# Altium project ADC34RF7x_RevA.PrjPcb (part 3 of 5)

## Sheet ADC34RF7x_MUX_RevA.SchDoc: MUXes
size 431 x 279 mm; Date: Not shown in title block; ApprovedBy: Not shown in title block; CheckedBy: Not shown in title block; Author: Not shown in title block; CompanyName: Not shown in title block; DrawnBy: CW; Engineer: Not shown in title block; Organization: Not shown in title block; Address1: Not shown in title block; Address2: Not shown in title block; Address3: Not shown in title block; Address4: Not shown in title block; DocumentNumber: 10; Revision: Use project parameter SCH_Rev; SheetNumber: 10; SheetTotal: 19; PageSetup: Record=PageOptions¦CenterHorizontal=True¦CenterVertical=True¦PrintScale=1.00¦XCorrection=1.00¦YCorrection=1.00¦PrintKind=0¦BorderSize=5000000¦LeftOffset=0¦BottomOffset=0¦Orientation=2¦PaperLength=1000¦PaperWidth=1000¦Scale=100¦PaperSource=15¦PrintQuality=600¦MediaType=1¦DitherType=10¦PaperKind=Letter¦PrintScaleMode=1
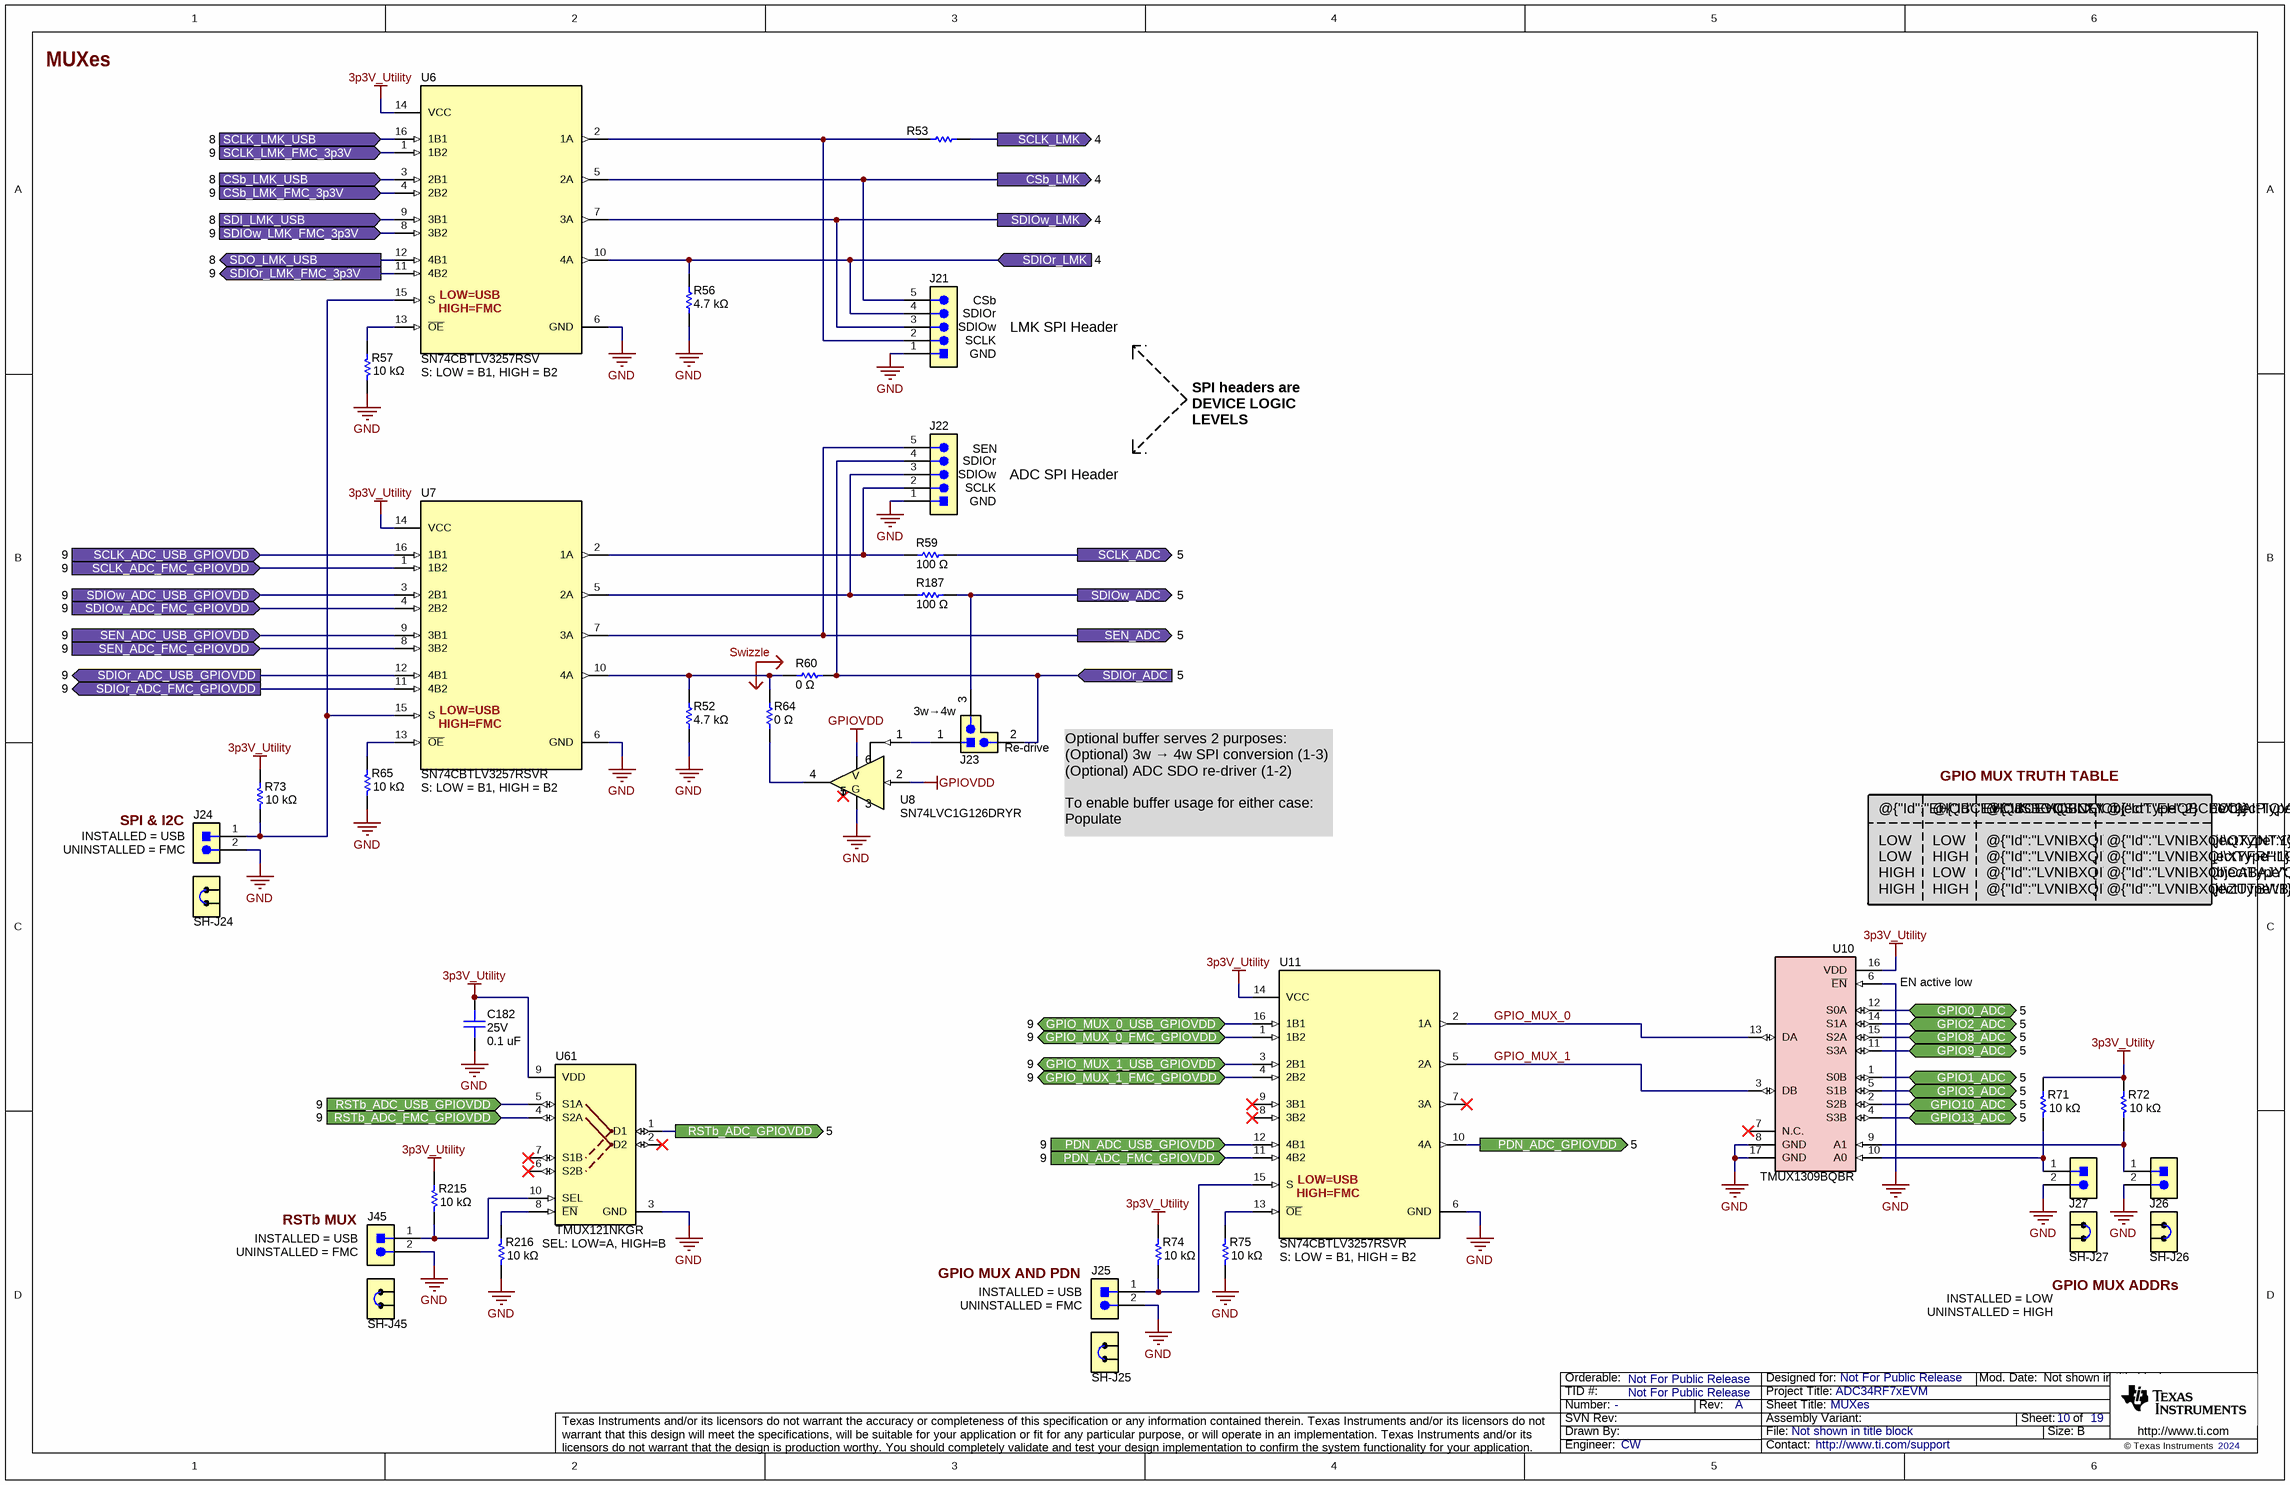
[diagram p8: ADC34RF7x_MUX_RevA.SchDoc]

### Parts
?  Swizzle  (graphical)
C182  value 0.1 uF  Voltage - Rated: 25V  [0201_cap]  (hidden comment: C0603X5R1E104K030BB)
J21  Text5: CSb  Text4: SDIOr  Text3: SDIOw  Text2: SCLK  Text1: GND  [HDR_5x1_TH_VT_50mil]  (hidden comment: GRPB051VWVN-RC)
J22  Text5: SEN  Text4: SDIOr  Text3: SDIOw  Text2: SCLK  Text1: GND  [HDR_5x1_TH_VT_50mil]  (hidden comment: GRPB051VWVN-RC)
J23  Text3: 3w→4w  Text2: Re-drive  [l-header]  (hidden comment: L-Header)
J24  GRPB021VWVN-RC  [PBC02SAAN]  (value not drawn)
J25  GRPB021VWVN-RC  [PBC02SAAN]  (value not drawn)
J26  GRPB021VWVN-RC  [PBC02SAAN]  (value not drawn)
J27  GRPB021VWVN-RC  [PBC02SAAN]  (value not drawn)
J45  GRPB021VWVN-RC  [PBC02SAAN]  (value not drawn)
R52  value 4.7 kΩ  [0201]  (hidden comment: ERJ-1GNF4701C)
R53  ERJ-1GNF1000C  [0201]  (value not drawn)
R56  value 4.7 kΩ  [0201]  (hidden comment: ERJ-1GNF4701C)
R57  value 10 kΩ  [0201]  (hidden comment: ERJ-1GNF1002C)
R59  value 100 Ω  [0201]  (hidden comment: ERJ-1GNF1000C)
R60  value 0 Ω  [0402L]  (hidden comment: ERJ-2GE0R00X)
R64  value 0 Ω  [0402L]  (hidden comment: ERJ-2GE0R00X)
R65  value 10 kΩ  [0201]  (hidden comment: ERJ-1GNF1002C)
R71  value 10 kΩ  [0201]  (hidden comment: ERJ-1GNF1002C)
R72  value 10 kΩ  [0201]  (hidden comment: ERJ-1GNF1002C)
R73  value 10 kΩ  [0201]  (hidden comment: ERJ-1GNF1002C)
R74  value 10 kΩ  [0201]  (hidden comment: ERJ-1GNF1002C)
R75  value 10 kΩ  [0201]  (hidden comment: ERJ-1GNF1002C)
R187  value 100 Ω  [0201]  (hidden comment: ERJ-1GNF1000C)
R215  value 10 kΩ  [0201]  (hidden comment: ERJ-1GNF1002C)
R216  value 10 kΩ  [0201]  (hidden comment: ERJ-1GNF1002C)
SH-J24  SPC02SYAN  [SPC02SYAN]  (value not drawn)
SH-J25  SPC02SYAN  [SPC02SYAN]  (value not drawn)
SH-J26  SPC02SYAN  [SPC02SYAN]  (value not drawn)
SH-J27  SPC02SYAN  [SPC02SYAN]  (value not drawn)
SH-J45  SPC02SYAN  [SPC02SYAN]  (value not drawn)
U6  SN74CBTLV3257RSV  Text1: S: LOW = B1, HIGH = B2  [RSV0016A]
U7  SN74CBTLV3257RSVR  Text1: S: LOW = B1, HIGH = B2  [RSV0016A]
U8  SN74LVC1G126DRYR  [DRY0006A]
U10  TMUX1309BQBR  [BQB0016A-MFG]
U11  SN74CBTLV3257RSVR  Text1: S: LOW = B1, HIGH = B2  [RSV0016A]
U61  TMUX121NKGR  Text1: SEL: LOW=A, HIGH=B  [NKG0010A]

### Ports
CSb_LMK (out, see 4), CSb_LMK_FMC_3p3V (in, see 9), CSb_LMK_USB (in, see 8), GPIO0_ADC (bidir, see 5), GPIO1_ADC (bidir, see 5), GPIO2_ADC (bidir, see 5), GPIO3_ADC (bidir, see 5), GPIO8_ADC (bidir, see 5), GPIO9_ADC (bidir, see 5), GPIO10_ADC (bidir, see 5), GPIO13_ADC (bidir, see 5), GPIO_MUX_0_FMC_GPIOVDD (bidir, see 9), GPIO_MUX_0_USB_GPIOVDD (bidir, see 9), GPIO_MUX_1_FMC_GPIOVDD (bidir, see 9), GPIO_MUX_1_USB_GPIOVDD (bidir, see 9), PDN_ADC_FMC_GPIOVDD (in, see 9), PDN_ADC_GPIOVDD (out, see 5), PDN_ADC_USB_GPIOVDD (in, see 9), RSTb_ADC_FMC_GPIOVDD (in, see 9), RSTb_ADC_GPIOVDD (out, see 5), RSTb_ADC_USB_GPIOVDD (in, see 9), SCLK_ADC (out, see 5), SCLK_ADC_FMC_GPIOVDD (in, see 9), SCLK_ADC_USB_GPIOVDD (in, see 9), SCLK_LMK (out, see 4), SCLK_LMK_FMC_3p3V (in, see 9), SCLK_LMK_USB (in, see 8), SDI_LMK_USB (in, see 8), SDIOr_ADC (in, see 5), SDIOr_ADC_FMC_GPIOVDD (out, see 9), SDIOr_ADC_USB_GPIOVDD (out, see 9), SDIOr_LMK (in, see 4), SDIOr_LMK_FMC_3p3V (out, see 9), SDIOw_ADC (out, see 5), SDIOw_ADC_FMC_GPIOVDD (in, see 9), SDIOw_ADC_USB_GPIOVDD (in, see 9), SDIOw_LMK (out, see 4), SDIOw_LMK_FMC_3p3V (in, see 9), SDO_LMK_USB (out, see 8), SEN_ADC (out, see 5), SEN_ADC_FMC_GPIOVDD (in, see 9), SEN_ADC_USB_GPIOVDD (in, see 9)

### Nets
3p3V_Utility: C182.2 R71.2 R72.2 R73.2 R74.2 R215.2 U6.14(VCC) U7.14(VCC) U10.16(VDD) U11.14(VCC) U61.9(VDD)
GND: C182.1 J21.1 J22.1 J24.2 J25.2 J26.2 J27.2 J45.2 R52.1 R56.1 R57.1 R65.1 R75.1 R216.1 U6.6(GND) U7.6(GND) U8.3(GND) U10.6(~{EN}) U10.8(GND) U10.17(GND) U11.6(GND) U61.3(GND)
GPIOVDD: U8.2(A) U8.6(VCC)
CSb_LMK: J21.5 U6.5(2A) ; port CSb_LMK
CSb_LMK_FMC_3p3V: U6.4(2B2) ; port CSb_LMK_FMC_3p3V
CSb_LMK_USB: U6.3(2B1) ; port CSb_LMK_USB
GPIO0_ADC: U10.12(S0A) ; port GPIO0_ADC
GPIO1_ADC: U10.1(S0B) ; port GPIO1_ADC
GPIO2_ADC: U10.14(S1A) ; port GPIO2_ADC
GPIO3_ADC: U10.5(S1B) ; port GPIO3_ADC
GPIO8_ADC: U10.15(S2A) ; port GPIO8_ADC
GPIO9_ADC: U10.11(S3A) ; port GPIO9_ADC
GPIO10_ADC: U10.2(S2B) ; port GPIO10_ADC
GPIO13_ADC: U10.4(S3B) ; port GPIO13_ADC
GPIO_MUX_0: U10.13(DA) U11.2(1A)
GPIO_MUX_0_FMC_GPIOVDD: U11.1(1B2) ; port GPIO_MUX_0_FMC_GPIOVDD
GPIO_MUX_0_USB_GPIOVDD: U11.16(1B1) ; port GPIO_MUX_0_USB_GPIOVDD
GPIO_MUX_1: U10.3(DB) U11.5(2A)
GPIO_MUX_1_FMC_GPIOVDD: U11.4(2B2) ; port GPIO_MUX_1_FMC_GPIOVDD
GPIO_MUX_1_USB_GPIOVDD: U11.3(2B1) ; port GPIO_MUX_1_USB_GPIOVDD
PDN_ADC_FMC_GPIOVDD: U11.11(4B2) ; port PDN_ADC_FMC_GPIOVDD
PDN_ADC_GPIOVDD: U11.10(4A) ; port PDN_ADC_GPIOVDD
PDN_ADC_USB_GPIOVDD: U11.12(4B1) ; port PDN_ADC_USB_GPIOVDD
RSTb_ADC_FMC_GPIOVDD: U61.4(S2A) ; port RSTb_ADC_FMC_GPIOVDD
RSTb_ADC_GPIOVDD: U61.1(D1) ; port RSTb_ADC_GPIOVDD
RSTb_ADC_USB_GPIOVDD: U61.5(S1A) ; port RSTb_ADC_USB_GPIOVDD
SCLK_ADC: R59.2 ; port SCLK_ADC
SCLK_ADC_FMC_GPIOVDD: U7.1(1B2) ; port SCLK_ADC_FMC_GPIOVDD
SCLK_ADC_USB_GPIOVDD: U7.16(1B1) ; port SCLK_ADC_USB_GPIOVDD
SCLK_LMK: R53.1 ; port SCLK_LMK
SCLK_LMK_FMC_3p3V: U6.1(1B2) ; port SCLK_LMK_FMC_3p3V
SCLK_LMK_USB: U6.16(1B1) ; port SCLK_LMK_USB
SDI_LMK_USB: U6.9(3B1) ; port SDI_LMK_USB
SDIOr_ADC: J22.4 J23.2 R60.2 ; port SDIOr_ADC
SDIOr_ADC_FMC_GPIOVDD: U7.11(4B2) ; port SDIOr_ADC_FMC_GPIOVDD
SDIOr_ADC_USB_GPIOVDD: U7.12(4B1) ; port SDIOr_ADC_USB_GPIOVDD
SDIOr_LMK: J21.4 R56.2 U6.10(4A) ; port SDIOr_LMK
SDIOr_LMK_FMC_3p3V: U6.11(4B2) ; port SDIOr_LMK_FMC_3p3V
SDIOw_ADC: J23.3 R187.2 ; port SDIOw_ADC
SDIOw_ADC_FMC_GPIOVDD: U7.4(2B2) ; port SDIOw_ADC_FMC_GPIOVDD
SDIOw_ADC_USB_GPIOVDD: U7.3(2B1) ; port SDIOw_ADC_USB_GPIOVDD
SDIOw_LMK: J21.3 U6.7(3A) ; port SDIOw_LMK
SDIOw_LMK_FMC_3p3V: U6.8(3B2) ; port SDIOw_LMK_FMC_3p3V
SDO_LMK_USB: U6.12(4B1) ; port SDO_LMK_USB
SEN_ADC: J22.5 U7.7(3A) ; port SEN_ADC
SEN_ADC_FMC_GPIOVDD: U7.8(3B2) ; port SEN_ADC_FMC_GPIOVDD
SEN_ADC_USB_GPIOVDD: U7.9(3B1) ; port SEN_ADC_USB_GPIOVDD
NetJ21_2: J21.2 R53.2 U6.2(1A)
NetJ22_2: J22.2 R59.1 U7.2(1A)
NetJ22_3: J22.3 R187.1 U7.5(2A)
NetJ23_1: J23.1 U8.1(~{OE})
NetJ24_1: J24.1 R73.1 U6.15(S) U7.15(S)
NetJ25_1: J25.1 R74.1 U11.15(S)
NetJ26_1: J26.1 R72.1 U10.9(A1)
NetJ27_1: J27.1 R71.1 U10.10(A0)
NetJ45_1: J45.1 R215.1 U61.10(SEL)
NetR52_2: R52.2 R60.1 R64.2 U7.10(4A)
NetR57_2: R57.2 U6.13(~{OE})
NetR64_1: R64.1 U8.4(Y)
NetR65_2: R65.2 U7.13(~{OE})
NetR75_2: R75.2 U11.13(~{OE})
NetR216_2: R216.2 U61.8(~{EN})

Not connected (* = marked no-connect by the designer): U8 5(NC)*; U10 7(N.C.)*; U11 7(3A)* 8(3B2)* 9(3B1)*; U61 2(D2)* 6(S2B)* 7(S1B)*

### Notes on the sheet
- (near U6) LOW=USB
- (near U6) HIGH=FMC
- LMK SPI Header
- SPI headers are DEVICE LOGIC LEVELS
- ADC SPI Header
- (near U7) LOW=USB
- (near U7) HIGH=FMC
- (near J24) SPI & I2C
- (near J24) INSTALLED = USB
- Optional buffer serves 2 purposes:
  (Optional) 3w → 4w SPI conversion (1-3)
  (Optional) ADC SDO re-driver (1-2)
  To enable buffer usage for either case: Populate @{"Id":"EHQBCEVC\QQRHBLRB","ObjectType":2} and depopulate @{"Id":"EHQBCEVC\ZQNBUIIU","ObjectType":2}
- GPIO MUX TRUTH TABLE
- UNINSTALLED = FMC
- @{"Id":"EHQBCEVC\JSBOQSIN","ObjectType":2}
  LOW
  LOW
  HIGH
  HIGH
- @{"Id":"EHQBCEVC\FLXYZYRI","ObjectType":2}
  LOW
  HIGH
  LOW
  HIGH
- @{"Id":"EHQBCEVC\FQXZMCJW","ObjectType":1}
  @{"Id":"LVNIBXQI\KMIXACKC","ObjectType":1}
  @{"Id":"LVNIBXQI\CEYJVZJK","ObjectType":1}
  @{"Id":"LVNIBXQI\UZKQOAMN","ObjectType":1}
  @{"Id":"LVNIBXQI\EZFJRBJM","ObjectType":1}
- @{"Id":"EHQBCEVC\AIPIQVSM","ObjectType":1}
  @{"Id":"LVNIBXQI\QXZNTYOS","ObjectType":1}
  @{"Id":"LVNIBXQI\XYFRHLOS","ObjectType":1}
  @{"Id":"LVNIBXQI\CABAJYQK","ObjectType":1}
  @{"Id":"LVNIBXQI\ZUTBWBLA","ObjectType":1}
- (near U10) EN active low
- (near J45) RSTb MUX
- (near J45) INSTALLED = USB
- (near U11) LOW=USB
- (near U11) HIGH=FMC
- (near J25) GPIO MUX AND PDN
- (near J25) INSTALLED = USB
- INSTALLED = LOW
- GPIO MUX ADDRs
- UNINSTALLED = HIGH

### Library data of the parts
? = Swizzle: Schematic notation to show that the pads of two components should be overlapped
C182 = capcc01294: CAP CER 0.1UF 25V X5R 0201; Manufacturer: TDK Corporation; CompType: Capacitor Ceramic; Tolerance: ±10%; SizeX_mm: 0.6; SizeY_mm: 0.3; SizeZ_mm: 0.33
J21 J22 = GRPB051VWVN-RC: Header, 50mil, 5x1, Gold, TH; Manufacturer: Sullins Connector Solutions; Pitch (mm): 1.27
J23 = L-Header: "L" Configuration Headers Connector Header Through Hole 3 position 100mils; UniqueID: cmp00511; CompType: Wire Housing; Text1: BufferIn
J24-J27 J45 = TSW-102-14-L-S: Header, 100mil, 2x1, Gold, TH; Manufacturer: Samtec; Alt Manufacturer: Sullins Connector Solutions; UniqueID: cmp00014; Pitch (mm): 2.54
R52 R56 = RSMD020100508: RES SMD 4.7K OHM 1% 1/20W 0201; Manufacturer: Panasonic Electronic Components; CompType: Resistor SMD; Power (Watts): 0.05W, 1/20W; Temperature Coefficient: ±200ppm/°C
R53 = RSMD020100289: RES SMD 100 OHM 1% 1/20W 0201; Manufacturer: Panasonic Electronic Components; Value: 100 Ω; CompType: Resistor SMD; Power (Watts): 0.05W, 1/20W; Temperature Coefficient: ±200ppm/°C
R57 R65 R71-R75 R215 R216 = RSMD020100762: RES SMD 10K OHM 1% 1/20W 0201; Manufacturer: Panasonic Electronic Components; CompType: Resistor SMD; Power (Watts): 0.05W, 1/20W; Temperature Coefficient: ±200ppm/°C
R59 R187 = RSMD020100289: RES SMD 100 OHM 1% 1/20W 0201; Manufacturer: Panasonic Electronic Components; CompType: Resistor SMD; Power (Watts): 0.05W, 1/20W; Temperature Coefficient: ±200ppm/°C
R60 R64 = RSMD040200001: RES SMD 0 OHM JUMPER 1/10W 0402; Manufacturer: Panasonic Electronic Components; CompType: Resistor SMD; Power (Watts): 0.1W, 1/10W; SizeX_mm: 1; SizeY_mm: 0.5; SizeZ_mm: 0.4
SH-J24-SH-J27 SH-J45 = cmp00093: 2 (1 x 2) Position Shunt Connector Black Closed Top 0.100" (2.54mm) Gold; Manufacturer: Sullins; Value: 1x2; Note: You can "mate" this to a header by matching the designator.  i.e. use SH-J3 for header J3; Pitch (mm): 2.54
U6 = SN74CBTLV3257RSV: Low-Voltage 4-Bit 1-of-2 FET Multiplexer/Demultiplexe; PartNumber: SN74CBTLV3257RSVR; Manufacturer: Texas Instruments; UniqueID: cmp00269; CompType: MUX
U7 U11 = SN74CBTLV3257RSV: Low-Voltage 4-Bit 1-of-2 FET Multiplexer/Demultiplexe; Manufacturer: Texas Instruments; UniqueID: cmp00269; CompType: MUX
U8 = cmp00344: Low-Power Single Bus Buffer Gate With Tri-State Output; Manufacturer: Texas Instruments
U10 = TMUX1309BQBR: Bidirectional 4:1, 2-Channel Multiplexer with Injection Current Control; Manufacturer: Texas Instruments
U61 = TMUX121NKGR: 2-pF, 3.3-V, 2:1 (SPDT), 2-channel, switch with 1.8-V compatible logic; Manufacturer: Texas Instruments

## Sheet ADC34RF7x_SYSREF_FPGA_MUX_RevA.SchDoc
size 431 x 279 mm; Date: Not shown in title block; ApprovedBy: Not shown in title block; CheckedBy: Not shown in title block; Author: Not shown in title block; CompanyName: Not shown in title block; Engineer: Not shown in title block; Organization: Not shown in title block; Address1: Not shown in title block; Address2: Not shown in title block; Address3: Not shown in title block; Address4: Not shown in title block; DocumentNumber: 1; Revision: Use project parameter SCH_Rev; SheetNumber: 11; SheetTotal: 19; PageSetup: Record=PageOptions¦CenterHorizontal=True¦CenterVertical=True¦PrintScale=1.00¦XCorrection=1.00¦YCorrection=1.00¦PrintKind=0¦BorderSize=5000000¦LeftOffset=0¦BottomOffset=0¦Orientation=2¦PaperLength=1000¦PaperWidth=1000¦Scale=100¦PaperSource=15¦PrintQuality=600¦MediaType=1¦DitherType=10¦PaperKind=Letter¦PrintScaleMode=1
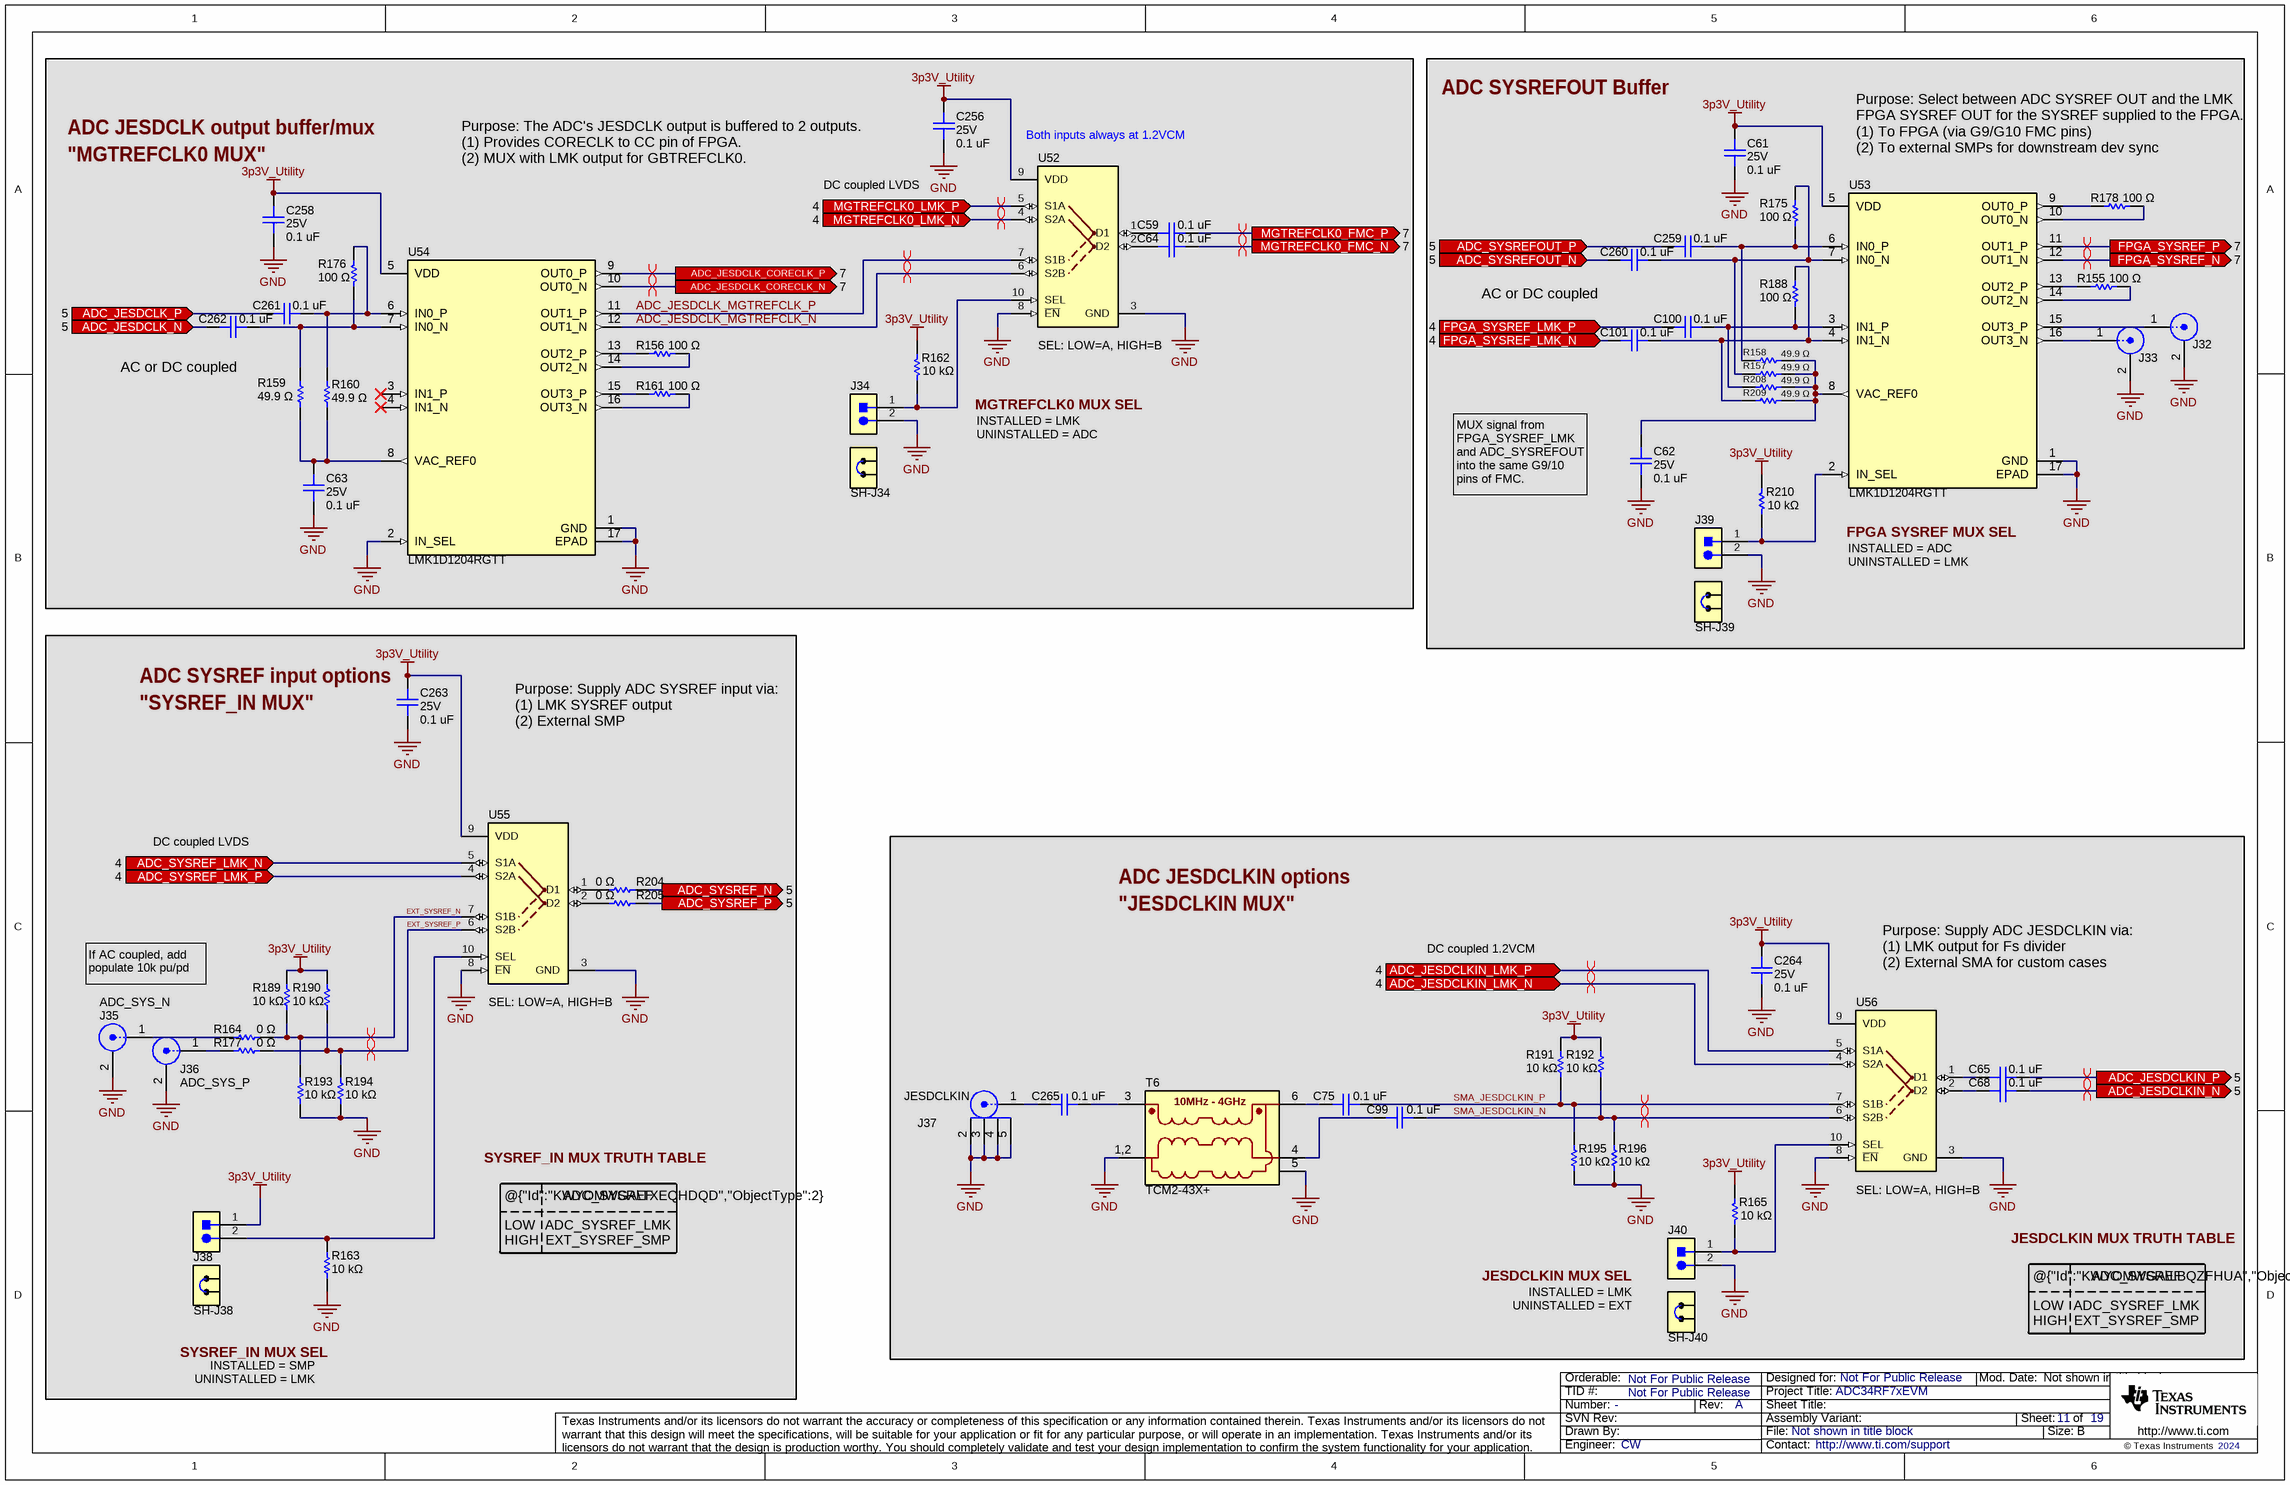
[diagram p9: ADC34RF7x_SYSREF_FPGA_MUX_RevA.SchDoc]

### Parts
C59  value 0.1 uF  [0201_cap]  (hidden comment: C0603X5R1E104K030BB)
C61  value 0.1 uF  Voltage - Rated: 25V  [0201_cap]  (hidden comment: C0603X5R1E104K030BB)
C62  value 0.1 uF  Voltage - Rated: 25V  [0201_cap]  (hidden comment: C0603X5R1E104K030BB)
C63  value 0.1 uF  Voltage - Rated: 25V  [0201_cap]  (hidden comment: C0603X5R1E104K030BB)
C64  value 0.1 uF  [0201_cap]  (hidden comment: C0603X5R1E104K030BB)
C65  value 0.1 uF  [0201_cap]  (hidden comment: C0603X5R1E104K030BB)
C68  value 0.1 uF  [0201_cap]  (hidden comment: C0603X5R1E104K030BB)
C75  value 0.1 uF  [0201_cap]  (hidden comment: 0201BB104KW160)
C99  value 0.1 uF  [0201_cap]  (hidden comment: 0201BB104KW160)
C100  value 0.1 uF  [0201_cap]  (hidden comment: C0603X5R1E104K030BB)
C101  value 0.1 uF  [0201_cap]  (hidden comment: C0603X5R1E104K030BB)
C256  value 0.1 uF  Voltage - Rated: 25V  [0201_cap]  (hidden comment: C0603X5R1E104K030BB)
C258  value 0.1 uF  Voltage - Rated: 25V  [0201_cap]  (hidden comment: C0603X5R1E104K030BB)
C259  value 0.1 uF  [0201_cap]  (hidden comment: C0603X5R1E104K030BB)
C260  value 0.1 uF  [0201_cap]  (hidden comment: C0603X5R1E104K030BB)
C261  value 0.1 uF  [0201_cap]  (hidden comment: C0603X5R1E104K030BB)
C262  value 0.1 uF  [0201_cap]  (hidden comment: C0603X5R1E104K030BB)
C263  value 0.1 uF  Voltage - Rated: 25V  [0201_cap]  (hidden comment: C0603X5R1E104K030BB)
C264  value 0.1 uF  Voltage - Rated: 25V  [0201_cap]  (hidden comment: C0603X5R1E104K030BB)
C265  value 0.1 uF  [0201_cap]  (hidden comment: 0201BB104KW160)
J32  0853050232  [Molex_0853050232]  (value not drawn)
J33  0853050232  [Molex_0853050232]  (value not drawn)
J34  GRPB021VWVN-RC  [PBC02SAAN]  (value not drawn)
J35  Text1: ADC_SYS_N  [Molex_0853050232]  (hidden comment: 0853050232)
J36  Text1: ADC_SYS_P  [Molex_0853050232]  (hidden comment: 0853050232)
J37  Text1: JESDCLKIN  [FP-132134-15_CONN_SMA_JACK-MFG]  (hidden comment: 132134-15)
J38  GRPB021VWVN-RC  [PBC02SAAN]  (value not drawn)
J39  GRPB021VWVN-RC  [PBC02SAAN]  (value not drawn)
J40  GRPB021VWVN-RC  [PBC02SAAN]  (value not drawn)
R155  value 100 Ω  [0201]  (hidden comment: ERJ-1GNF1000C)
R156  value 100 Ω  [0201]  (hidden comment: ERJ-1GNF1000C)
R157  value 49.9 Ω  [0201]  (hidden comment: ERJ-1GNF49R9C)
R158  value 49.9 Ω  [0201]  (hidden comment: ERJ-1GNF49R9C)
R159  value 49.9 Ω  [0201]  (hidden comment: ERJ-1GNF49R9C)
R160  value 49.9 Ω  [0201]  (hidden comment: ERJ-1GNF49R9C)
R161  value 100 Ω  [0201]  (hidden comment: ERJ-1GNF1000C)
R162  value 10 kΩ  [0201]  (hidden comment: ERJ-1GNF1002C)
R163  value 10 kΩ  [0201]  (hidden comment: ERJ-1GNF1002C)
R164  value 0 Ω  [0201]  (hidden comment: ERJ-1GN0R00C)
R165  value 10 kΩ  [0201]  (hidden comment: ERJ-1GNF1002C)
R175  value 100 Ω  [0201]  (hidden comment: ERJ-1GNF1000C)
R176  value 100 Ω  [0201]  (hidden comment: ERJ-1GNF1000C)
R177  value 0 Ω  [0201]  (hidden comment: ERJ-1GN0R00C)
R178  value 100 Ω  [0201]  (hidden comment: ERJ-1GNF1000C)
R188  value 100 Ω  [0201]  (hidden comment: ERJ-1GNF1000C)
R189  value 10 kΩ  [0201]  (hidden comment: ERJ-1GNF1002C)
R190  value 10 kΩ  [0201]  (hidden comment: ERJ-1GNF1002C)
R191  value 10 kΩ  [0201]  (hidden comment: ERJ-1GNF1002C)
R192  value 10 kΩ  [0201]  (hidden comment: ERJ-1GNF1002C)
R193  value 10 kΩ  [0201]  (hidden comment: ERJ-1GNF1002C)
R194  value 10 kΩ  [0201]  (hidden comment: ERJ-1GNF1002C)
R195  value 10 kΩ  [0201]  (hidden comment: ERJ-1GNF1002C)
R196  value 10 kΩ  [0201]  (hidden comment: ERJ-1GNF1002C)
R204  value 0 Ω  [0201]  (hidden comment: ERJ-1GN0R00C)
R205  value 0 Ω  [0201]  (hidden comment: ERJ-1GN0R00C)
R208  value 49.9 Ω  [0201]  (hidden comment: ERJ-1GNF49R9C)
R209  value 49.9 Ω  [0201]  (hidden comment: ERJ-1GNF49R9C)
R210  value 10 kΩ  [0201]  (hidden comment: ERJ-1GNF1002C)
SH-J34  SPC02SYAN  [SPC02SYAN]  (value not drawn)
SH-J38  SPC02SYAN  [SPC02SYAN]  (value not drawn)
SH-J39  SPC02SYAN  [SPC02SYAN]  (value not drawn)
SH-J40  SPC02SYAN  [SPC02SYAN]  (value not drawn)
T6  TCM2-43X+  [TCM2-43X+]
U52  Text1: SEL: LOW=A, HIGH=B  [NKG0010A]
U53  PartNumber: LMK1D1204RGTT  [RGT0016C]  (hidden comment: LMK1D1204)
U54  PartNumber: LMK1D1204RGTT  [RGT0016C]  (hidden comment: LMK1D1204)
U55  Text1: SEL: LOW=A, HIGH=B  [NKG0010A]
U56  Text1: SEL: LOW=A, HIGH=B  [NKG0010A]

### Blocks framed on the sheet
ADC SYSREFOUT Buffer: C61 C62 C100 C101 C259 C260 J32 J33 J39 R155 R157 R158 R175 R178 R188 R208-R210 SH-J39 U53

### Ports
ADC_JESDCLK_CORECLK_N (out, see 7), ADC_JESDCLK_CORECLK_P (out, see 7), ADC_JESDCLK_N (in, see 5), ADC_JESDCLK_P (in, see 5), ADC_JESDCLKIN_LMK_N (in, see 4), ADC_JESDCLKIN_LMK_P (in, see 4), ADC_JESDCLKIN_N (out, see 5), ADC_JESDCLKIN_P (out, see 5), ADC_SYSREF_LMK_N (in, see 4), ADC_SYSREF_LMK_P (in, see 4), ADC_SYSREF_N (out, see 5), ADC_SYSREF_P (out, see 5), ADC_SYSREFOUT_N (in, see 5), ADC_SYSREFOUT_P (in, see 5), FPGA_SYSREF_LMK_N (in, see 4), FPGA_SYSREF_LMK_P (in, see 4), FPGA_SYSREF_N (out, see 7), FPGA_SYSREF_P (out, see 7), MGTREFCLK0_FMC_N (out, see 7), MGTREFCLK0_FMC_P (out, see 7), MGTREFCLK0_LMK_N (in, see 4), MGTREFCLK0_LMK_P (in, see 4)

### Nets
3p3V_Utility: C61.2 C256.2 C258.2 C263.2 C264.2 J38.1 R162.2 R165.2 R189.2 R190.2 R191.2 R192.2 R210.2 U52.9(VDD) U53.5(VDD) U54.5(VDD) U55.9(VDD) U56.9(VDD)
GND: C61.1 C62.1 C63.1 C256.1 C258.1 C263.1 C264.1 J32.2 J33.2 J34.2 J35.2 J36.2 J37.2 J37.3 J37.4 J37.5 J39.2 J40.2 R163.1 R193.1 R194.1 R195.1 R196.1 T6.1,2(Primary) T6.5(NC) U52.3(GND) U52.8(~{EN}) U53.1(GND) U53.17(EPAD) U54.1(GND) U54.2(IN_SEL) U54.17(EPAD) U55.3(GND) U55.8(~{EN}) U56.3(GND) U56.8(~{EN})
ADC_JESDCLK_CORECLK_N: U54.10(OUT0_N) ; port ADC_JESDCLK_CORECLK_N
ADC_JESDCLK_CORECLK_P: U54.9(OUT0_P) ; port ADC_JESDCLK_CORECLK_P
ADC_JESDCLK_MGTREFCLK_N: U52.6(S2B) U54.12(OUT1_N)
ADC_JESDCLK_MGTREFCLK_P: U52.7(S1B) U54.11(OUT1_P)
ADC_JESDCLK_N: C262.2 ; port ADC_JESDCLK_N
ADC_JESDCLK_P: C261.2 ; port ADC_JESDCLK_P
ADC_JESDCLKIN_LMK_N: U56.4(S2A) ; port ADC_JESDCLKIN_LMK_N
ADC_JESDCLKIN_LMK_P: U56.5(S1A) ; port ADC_JESDCLKIN_LMK_P
ADC_JESDCLKIN_N: C68.1 ; port ADC_JESDCLKIN_N
ADC_JESDCLKIN_P: C65.1 ; port ADC_JESDCLKIN_P
ADC_SYSREF_LMK_N: U55.5(S1A) ; port ADC_SYSREF_LMK_N
ADC_SYSREF_LMK_P: U55.4(S2A) ; port ADC_SYSREF_LMK_P
ADC_SYSREF_N: R204.2 ; port ADC_SYSREF_N
ADC_SYSREF_P: R205.2 ; port ADC_SYSREF_P
ADC_SYSREFOUT_N: C260.2 ; port ADC_SYSREFOUT_N
ADC_SYSREFOUT_P: C259.2 ; port ADC_SYSREFOUT_P
EXT_SYSREF_N: R164.1 R189.1 R193.2 U55.7(S1B)
EXT_SYSREF_P: R177.1 R190.1 R194.2 U55.6(S2B)
FPGA_SYSREF_LMK_N: C101.2 ; port FPGA_SYSREF_LMK_N
FPGA_SYSREF_LMK_P: C100.2 ; port FPGA_SYSREF_LMK_P
FPGA_SYSREF_N: U53.12(OUT1_N) ; port FPGA_SYSREF_N
FPGA_SYSREF_P: U53.11(OUT1_P) ; port FPGA_SYSREF_P
MGTREFCLK0_FMC_N: C64.1 ; port MGTREFCLK0_FMC_N
MGTREFCLK0_FMC_P: C59.1 ; port MGTREFCLK0_FMC_P
MGTREFCLK0_LMK_N: U52.4(S2A) ; port MGTREFCLK0_LMK_N
MGTREFCLK0_LMK_P: U52.5(S1A) ; port MGTREFCLK0_LMK_P
SMA_JESDCLKIN_N: C99.1 R192.1 R196.2 U56.6(S2B)
SMA_JESDCLKIN_P: C75.1 R191.1 R195.2 U56.7(S1B)
NetC59_2: C59.2 U52.1(D1)
NetC62_2: C62.2 R157.1 R158.1 R208.1 R209.1 U53.8(VAC_REF0)
NetC63_2: C63.2 R159.1 R160.1 U54.8(VAC_REF0)
NetC64_2: C64.2 U52.2(D2)
NetC65_2: C65.2 U56.1(D1)
NetC68_2: C68.2 U56.2(D2)
NetC75_2: C75.2 T6.6(Secondary_Dot)
NetC99_2: C99.2 T6.4(Secondary)
NetC100_1: C100.1 R188.1 R208.2 U53.3(IN1_P)
NetC101_1: C101.1 R188.2 R209.2 U53.4(IN1_N)
NetC259_1: C259.1 R158.2 R175.2 U53.6(IN0_P)
NetC260_1: C260.1 R157.2 R175.1 U53.7(IN0_N)
NetC261_1: C261.1 R160.2 R176.2 U54.6(IN0_P)
NetC262_1: C262.1 R159.2 R176.1 U54.7(IN0_N)
NetC265_1: C265.1 T6.3(Primary_Dot)
NetC265_2: C265.2 J37.1
NetJ32_1: J32.1 U53.15(OUT3_P)
NetJ33_1: J33.1 U53.16(OUT3_N)
NetJ34_1: J34.1 R162.1 U52.10(SEL)
NetJ35_1: J35.1 R164.2
NetJ36_1: J36.1 R177.2
NetJ38_2: J38.2 R163.2 U55.10(SEL)
NetJ39_1: J39.1 R210.1 U53.2(IN_SEL)
NetJ40_1: J40.1 R165.1 U56.10(SEL)
NetR155_1: R155.1 U53.13(OUT2_P)
NetR155_2: R155.2 U53.14(OUT2_N)
NetR156_1: R156.1 U54.13(OUT2_P)
NetR156_2: R156.2 U54.14(OUT2_N)
NetR161_1: R161.1 U54.15(OUT3_P)
NetR161_2: R161.2 U54.16(OUT3_N)
NetR178_1: R178.1 U53.9(OUT0_P)
NetR178_2: R178.2 U53.10(OUT0_N)
NetR204_1: R204.1 U55.1(D1)
NetR205_1: R205.1 U55.2(D2)

Not connected (* = marked no-connect by the designer): U54 3(IN1_P)* 4(IN1_N)*

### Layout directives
differential pair: ADC_JESDCLK_CORECLK_N, ADC_JESDCLK_CORECLK_P, ADC_JESDCLK_MGTREFCLK_N, ADC_JESDCLK_MGTREFCLK_P, ADC_JESDCLKIN_LMK_N, ADC_JESDCLKIN_LMK_P, ADC_JESDCLKIN_N, ADC_JESDCLKIN_P, EXT_SYSREF_N, EXT_SYSREF_P, FPGA_SYSREF_N, FPGA_SYSREF_P, MGTREFCLK0_FMC_N, MGTREFCLK0_FMC_P, MGTREFCLK0_LMK_N, MGTREFCLK0_LMK_P, SMA_JESDCLKIN_N, SMA_JESDCLKIN_P

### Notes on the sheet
- ADC JESDCLK output buffer/mux
- (near C258) "MGTREFCLK0 MUX"
- (near U52) Both inputs always at 1.2VCM
- Purpose: Select between ADC SYSREF OUT and the LMK FPGA SYSREF OUT for the SYSREF supplied to the FPGA.
  (1) To FPGA (via G9/G10 FMC pins)
  (2) To external SMPs for downstream dev sync
- Purpose: The ADC's JESDCLK output is buffered to 2 outputs.
  (1) Provides CORECLK to CC pin of FPGA.
  (2) MUX with LMK output for GBTREFCLK0.
- (near C256) DC coupled LVDS
- AC or DC coupled
- (near C262) AC or DC coupled
- MGTREFCLK0 MUX SEL
- INSTALLED = LMK
- UNINSTALLED = ADC
- MUX signal from FPGA_SYSREF_LMK and ADC_SYSREFOUT into the same G9/10 pins of FMC.
- (near U53) FPGA SYSREF MUX SEL
- INSTALLED = ADC
- UNINSTALLED = LMK
- (near C263) ADC SYSREF input options
- "SYSREF_IN MUX"
- Purpose: Supply ADC SYSREF input via:
  (1) LMK SYSREF output
  (2) External SMP
- DC coupled LVDS
- ADC JESDCLKIN options
- "JESDCLKIN MUX"
- DC coupled 1.2VCM
- If AC coupled, add populate 10k pu/pd
- (near U56) Purpose: Supply ADC JESDCLKIN via:
  (1) LMK output for Fs divider
  (2) External SMA for custom cases
- (near T6) 10MHz - 4GHz
- SYSREF_IN MUX TRUTH TABLE
- JESDCLKIN MUX TRUTH TABLE
- @{"Id":"KWYOMWGA\TXEQHDQD","ObjectType":2}
  LOW
  HIGH
- ADC_SYSREF
  ADC_SYSREF_LMK
  EXT_SYSREF_SMP
- JESDCLKIN MUX SEL
- UNINSTALLED = EXT
- SYSREF_IN MUX SEL
- INSTALLED = SMP
- @{"Id":"KWYOMWGA\LBQZFHUA","ObjectType":2}
  LOW
  HIGH

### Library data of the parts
C59 C61-C65 C68 C100 C101 C256 C258-C264 = capcc01294: as C182 on sheet ADC34RF7x_MUX_RevA
C75 C99 C265 = 0201RFCaps0693: Broadband Capacitors; Manufacturer: Passive Plus; Alt PartNumber: GRM033C71C104ME14D; Alt Manufacturer: Murata Electronics; SizeZ_mm: 0.33; SizeY_mm: 0.3; CompType: Capactior RF; SizeX_mm: 0.58; Voltage - Rated: 16V; Tolerance: ±10%; Temperature Coefficient: C0G, NP0
J32 = cmp00032: SMP Connector Plug, Male Pin 50Ohm Surface Mount Solder; Manufacturer: Molex; SymbolCreator: a0799628; Cert_UL: Y; ContactFinish: Gold; CompType: RF Connector; CT: False; Voltage_V: 335V; Text1: ADC_SYSREFOUT_P
J33 = cmp00032: SMP Connector Plug, Male Pin 50Ohm Surface Mount Solder; Manufacturer: Molex; SymbolCreator: a0799628; Cert_UL: Y; ContactFinish: Gold; CompType: RF Connector; CT: False; Voltage_V: 335V; Text1: ADC_SYSREFOUT_N
J34 J38-J40 = TSW-102-14-L-S: as J24-J27 on sheet ADC34RF7x_MUX_RevA
J35 J36 = cmp00032: SMP Connector Plug, Male Pin 50Ohm Surface Mount Solder; Manufacturer: Molex; SymbolCreator: a0799628; Cert_UL: Y; ContactFinish: Gold; CompType: RF Connector; CT: False; Voltage_V: 335V
J37 = cmp00028: SMA Connector Jack, Female Socket 50Ohm Surface Mount, Through Hole Solder; Manufacturer: Amphenol RF; CompType: RF Connector
R155 R156 R161 R175 R176 R178 R188 = RSMD020100289: as R59 on sheet ADC34RF7x_MUX_RevA
R157-R160 R208 R209 = RSMD020100177: RES SMD 49.9 OHM 1% 1/20W 0201; Manufacturer: Panasonic Electronic Components; CompType: Resistor SMD; Power (Watts): 0.05W, 1/20W; Temperature Coefficient: ±200ppm/°C
R162 R163 R165 R189-R196 R210 = RSMD020100762: as R57 on sheet ADC34RF7x_MUX_RevA
R164 R177 R204 R205 = RSMD020101699: RES SMD 0 OHM JUMPER 1/20W 0201; Manufacturer: Panasonic Electronic Components; CompType: Resistor SMD; Power (Watts): 0.05W, 1/20W
SH-J34 SH-J38-SH-J40 = cmp00093: as SH-J24-SH-J27 on sheet ADC34RF7x_MUX_RevA
T6 = cmp00381: 1:2 CORE & WIRE Transformer, 10 - 4000 MHz, 50Ω; Manufacturer: Mini-Circuits; CompType: Balun
U52 U55 U56 = TMUX121NKGR: as U61 on sheet ADC34RF7x_MUX_RevA
U53 U54 = cmp00271: Texas Instruments; Manufacturer_Part_Number: LMK1D1204RGTR; CompType: Buffer

## Sheet ADC34RF7x_Power1_RevA.SchDoc: EVM Power 1
size 431 x 279 mm; Date: Not shown in title block; ApprovedBy: Not shown in title block; CheckedBy: Not shown in title block; Author: Not shown in title block; CompanyName: Not shown in title block; DrawnBy: CW; Engineer: Not shown in title block; Organization: Not shown in title block; Address1: Not shown in title block; Address2: Not shown in title block; Address3: Not shown in title block; Address4: Not shown in title block; DocumentNumber: 6; Revision: Use project parameter SCH_Rev; SheetNumber: 12; SheetTotal: 19; PageSetup: Record=PageOptions¦CenterHorizontal=True¦CenterVertical=True¦PrintScale=1.00¦XCorrection=1.00¦YCorrection=1.00¦PrintKind=0¦BorderSize=5000000¦LeftOffset=0¦BottomOffset=0¦Orientation=2¦PaperLength=1000¦PaperWidth=1000¦Scale=100¦PaperSource=15¦PrintQuality=600¦MediaType=1¦DitherType=10¦PaperKind=Letter¦PrintScaleMode=1
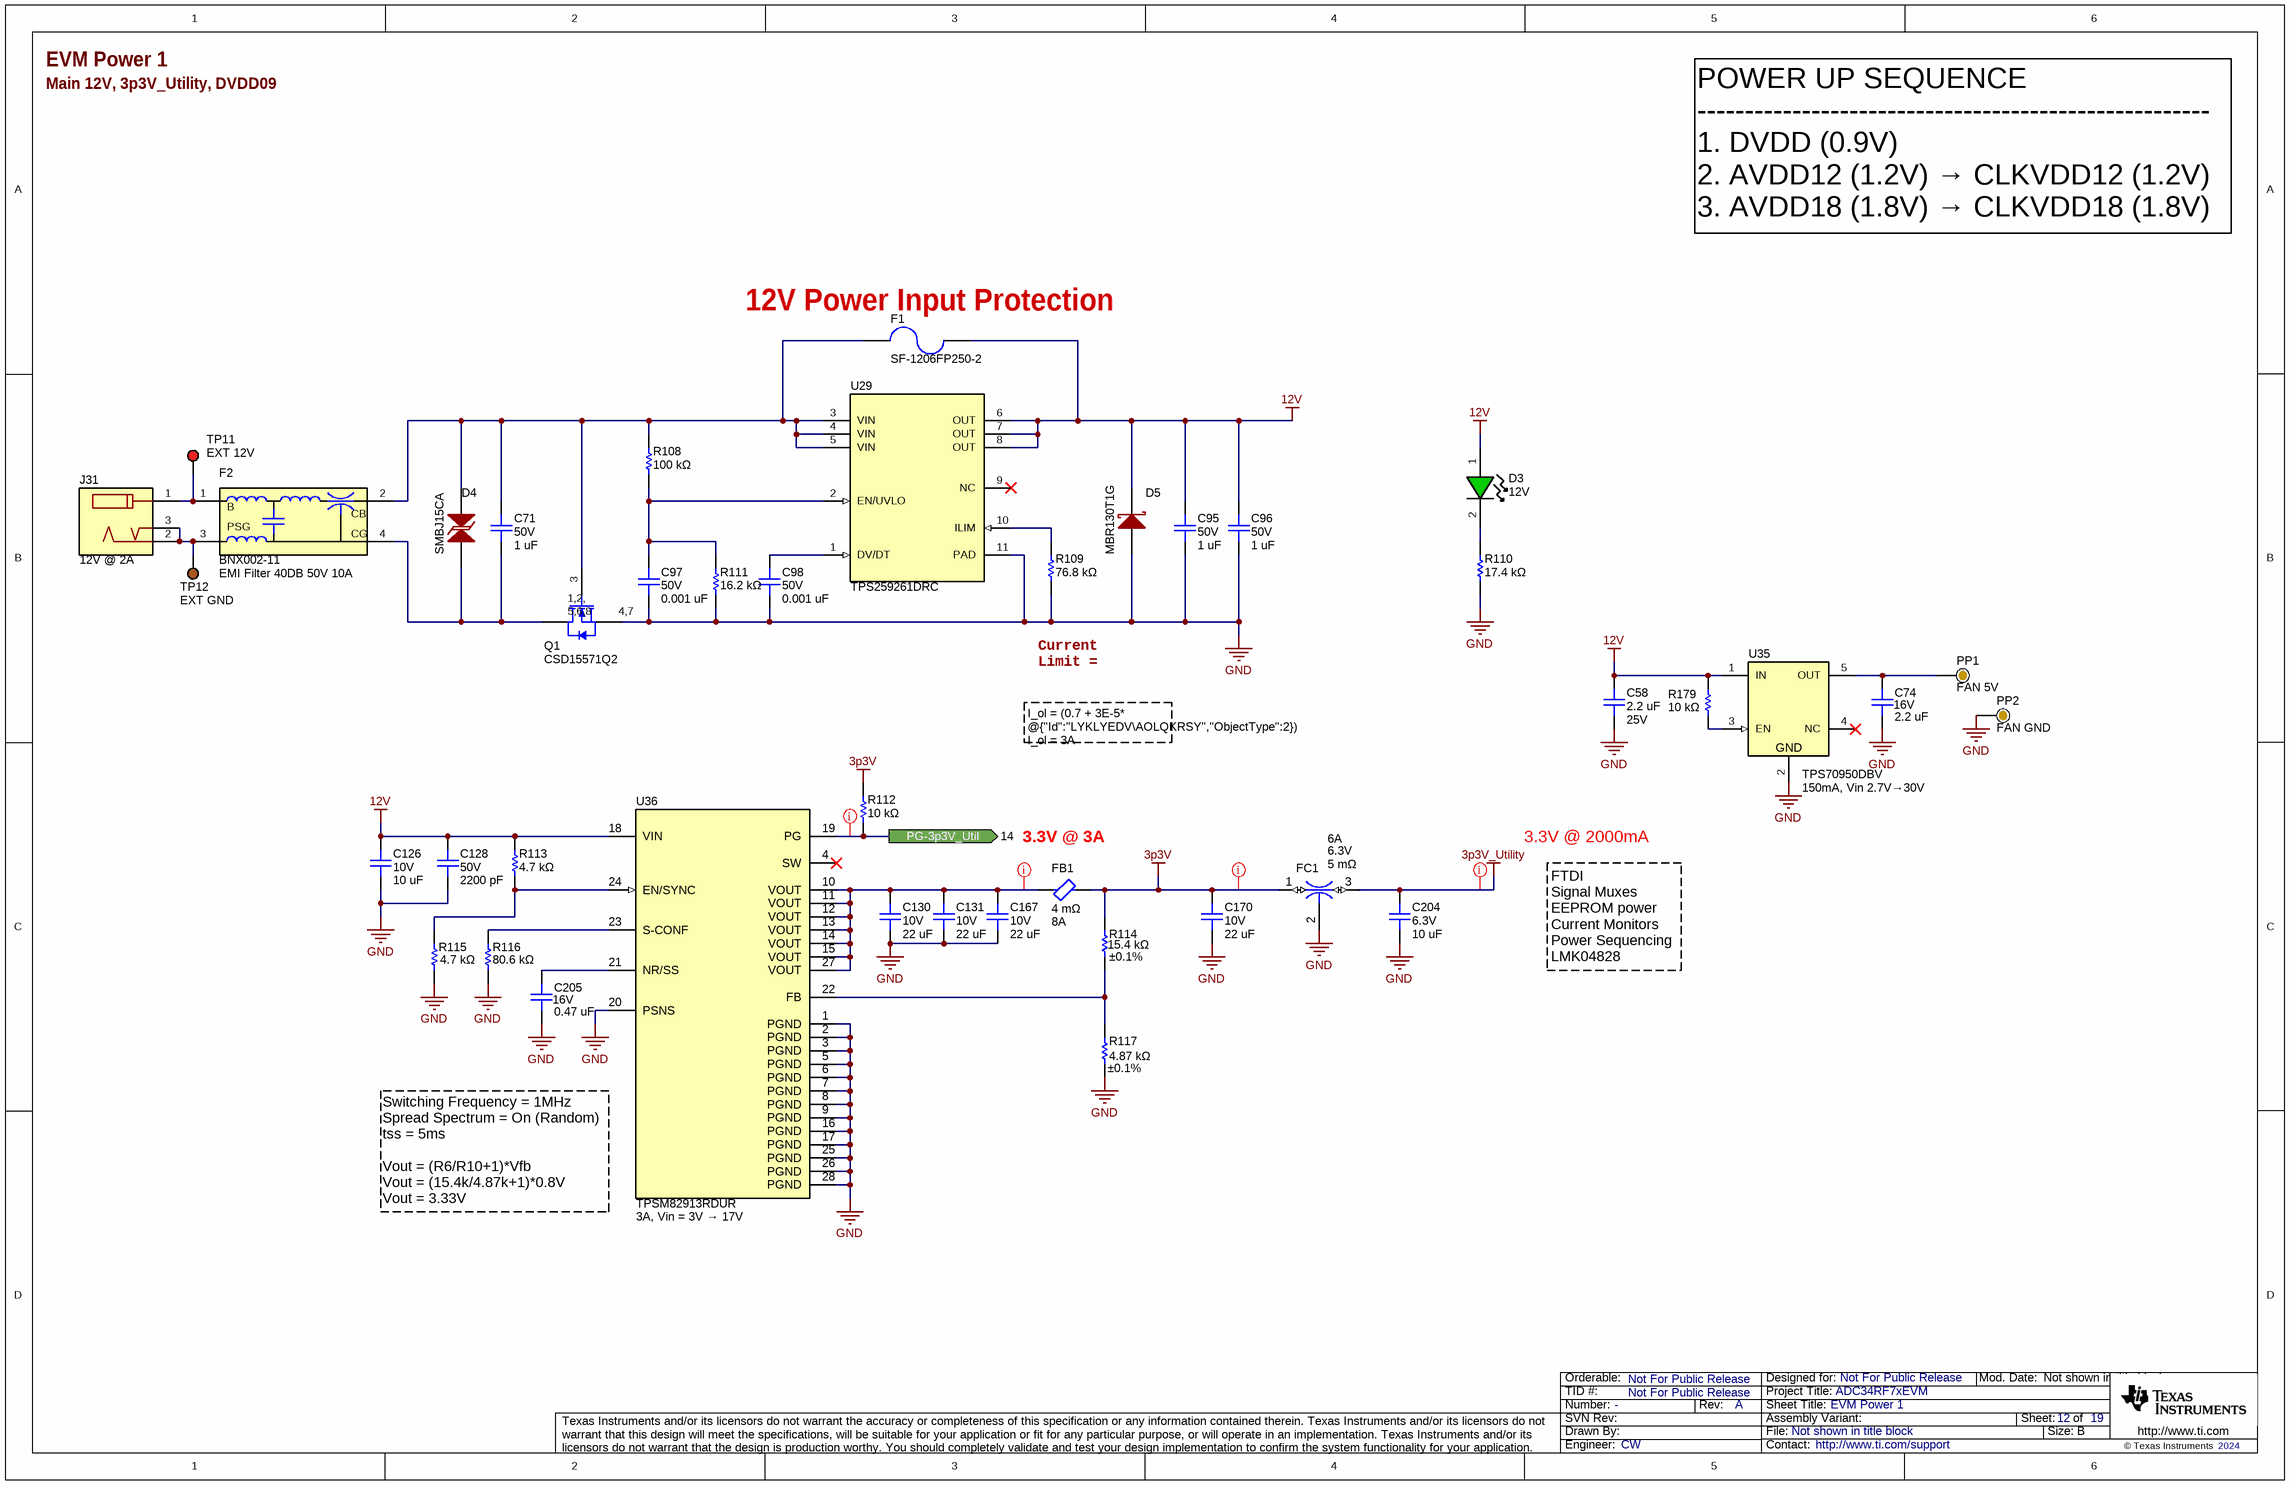
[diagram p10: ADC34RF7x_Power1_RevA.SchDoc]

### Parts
C58  value 2.2 uF  Voltage - Rated: 25V  [0402L_cap]  (hidden comment: C1005X5R1E225K050BC)
C71  value 1 uF  Voltage - Rated: 50V  [0805L_cap]  (hidden comment: C2012X7R1H105K125AB)
C74  value 2.2 uF  Voltage - Rated: 16V  [0402L_cap]  (hidden comment: C1005X6S1C225K050BC)
C95  value 1 uF  Voltage - Rated: 50V  [0805L_cap]  (hidden comment: C2012X7R1H105K125AB)
C96  value 1 uF  Voltage - Rated: 50V  [0805L_cap]  (hidden comment: C2012X7R1H105K125AB)
C97  value 0.001 uF  Voltage - Rated: 50V  [0603L_cap]  (hidden comment: CGA3E2X7R1H102K080AA)
C98  value 0.001 uF  Voltage - Rated: 50V  [0603L_cap]  (hidden comment: CGA3E2X7R1H102K080AA)
C126  value 10 uF  Voltage - Rated: 10V  [0603L_cap]  (hidden comment: 0603ZD106KAT2A)
C128  value 2200 pF  Voltage - Rated: 50V  [0402L_cap]  (hidden comment: 04025C222JAT2A)
C130  value 22 uF  Voltage - Rated: 10V  [0805L_cap]  (hidden comment: C2012X7S1A226M125AC)
C131  value 22 uF  Voltage - Rated: 10V  [0805L_cap]  (hidden comment: C2012X7S1A226M125AC)
C167  value 22 uF  Voltage - Rated: 10V  [0805L_cap]  (hidden comment: C2012X7S1A226M125AC)
C170  value 22 uF  Voltage - Rated: 10V  [0805L_cap]  (hidden comment: C2012X7S1A226M125AC)
C204  value 10 uF  Voltage - Rated: 6.3V  [0402L_cap]  (hidden comment: GRM155C80J106ME11D)
C205  value 0.47 uF  Voltage - Rated: 16V  [0402L_cap]  (hidden comment: C1005X7S1C474K050BC)
D3  Text1: 12V  [LED_LTST-C190-Green]  (hidden comment: LTST-C191TGKT)
D4  SMBJ15CA  [SMBJ15CA]
D5  MBR130T1G  [SOD-123]
F1  SF-1206FP250-2  [SF-1206F500M-2_1206]
F2  BNX002-11  Text1: EMI Filter 40DB 50V 10A  [FIL_BNX002-11]
FB1  Current: 8A  DCR: 4 mΩ  [0603L]  (hidden comment: BLE18PS080SN1D)
FC1  Voltage - Rated: 6.3V  Current: 6A  DCR: 5 mΩ  [NFM31PC]  (hidden comment: NFM31PC276B0J3L)
J31  Text1: 12V @ 2A  [RAPC722X]  (hidden comment: RAPC722X)
PP1  Text1: FAN 5V  [ProbePoint_TH_40mil]  (hidden comment: Probe Point)  (no BOM)
PP2  Text1: FAN GND  [ProbePoint_TH_40mil]  (hidden comment: Probe Point)  (no BOM)
Q1  CSD15571Q2  [DQK0006C]
R108  value 100 kΩ  [0402L]  (hidden comment: ERJ-2GEJ104X)
R109  value 76.8 kΩ  [0402L]  (hidden comment: ERJ-2RKF7682X)
R110  value 17.4 kΩ  [0402L]  (hidden comment: ERJ-2RKF1742X)
R111  value 16.2 kΩ  [0402L]  (hidden comment: ERJ-2RKF1622X)
R112  value 10 kΩ  [0402L]  (hidden comment: ERJ-PA2F1002X)
R113  value 4.7 kΩ  [0402L]  (hidden comment: ERJ-PA2F4701X)
R114  value 15.4 kΩ  Tolerance: ±0.1%  [0402L]  (hidden comment: ERA-2APB1542X)
R115  value 4.7 kΩ  [0402L]  (hidden comment: ERJ-PA2F4701X)
R116  value 80.6 kΩ  [0402L]  (hidden comment: ERJ-2RKF8062X)
R117  value 4.87 kΩ  Tolerance: ±0.1%  [0402L]  (hidden comment: ERA-2APB4871X)
R179  value 10 kΩ  [0402L]  (hidden comment: ERJ-PA2F1002X)
TP11  Text1: EXT 12V  [Keystone5010]  (hidden comment: 5010)
TP12  Text1: EXT GND  [Keystone5125]  (hidden comment: 5125)
U29  TPS259261DRC  [DRC0010J]
U35  TPS70950DBV  Text1: 150mA, Vin 2.7V→30V  [DBV0005A]
U36  TPSM82913RDUR  Text1: 3A, Vin = 3V → 17V  [RDU0028A]

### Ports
PG-3p3V_Util (out, see 14)

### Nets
3p3V: C170.1 FB1.2 FC1.1 R112.2 R114.2
3p3V_Utility: C204.2 FC1.3
12V: C58.2 C95.2 C96.2 C126.2 C128.1 D3.1(A) D5.1(K) F1.1 R113.1 R179.2 U29.6(OUT) U29.7(OUT) U29.8(OUT) U35.1(IN) U36.18(VIN)
GND: C58.1 C74.1 C95.1 C96.1 C97.1 C98.1 C126.1 C128.2 C130.2 C131.2 C167.2 C170.2 C204.1 C205.1 D5.2(A) FC1.2 PP2.1 Q1.4,7(S) R109.1 R110.1 R111.1 R115.2 R116.1 R117.1 U29.11(PAD) U35.2(GND) U36.1(PGND) U36.2(PGND) U36.3(PGND) U36.5(PGND) U36.6(PGND) U36.7(PGND) U36.8(PGND) U36.9(PGND) U36.16(PGND) U36.17(PGND) U36.20(PSNS) U36.25(PGND) U36.26(PGND) U36.28(PGND)
PG-3p3V_Util: R112.1 U36.19(PG) ; port PG-3p3V_Util
NetC71_1: C71.1 D4.2 F1.2 F2.2(CB) Q1.3(G) R108.2 U29.3(VIN) U29.4(VIN) U29.5(VIN)
NetC71_2: C71.2 D4.1 F2.4(CG) Q1.1,2,5,6,8(D)
NetC74_2: C74.2 PP1.1 U35.5(OUT)
NetC97_2: C97.2 R108.1 R111.2 U29.2(EN/UVLO)
NetC98_2: C98.2 U29.1(DV/DT)
NetC130_1: C130.1 C131.1 C167.1 FB1.1 U36.10(VOUT) U36.11(VOUT) U36.12(VOUT) U36.13(VOUT) U36.14(VOUT) U36.15(VOUT) U36.27(VOUT)
NetC205_2: C205.2 U36.21(NR/SS)
NetD3_2: D3.2(K) R110.2
NetF2_1: F2.1(B) J31.1 TP11.1
NetF2_3: F2.3(PSG) J31.2 J31.3 TP12.1
NetR109_2: R109.2 U29.10(ILIM)
NetR113_2: R113.2 R115.1 U36.24(EN/SYNC)
NetR114_1: R114.1 R117.2 U36.22(FB)
NetR116_2: R116.2 U36.23(S-CONF)
NetR179_1: R179.1 U35.3(EN)

Not connected (* = marked no-connect by the designer): U29 9(NC)*; U35 4(NC)*; U36 4(SW)*

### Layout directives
net class Power_3p3V_Utility: 3p3V, 3p3V_Utility, NetC130_1
net class Power sequencing: PG-3p3V_Util

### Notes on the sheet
- Main 12V, 3p3V_Utility, DVDD09
- POWER UP SEQUENCE
  ------------------------------------------------------
  1. DVDD (0.9V)
  2. AVDD12 (1.2V) → CLKVDD12 (1.2V)
  3. AVDD18 (1.8V) → CLKVDD18 (1.8V)
- (near F1) 12V Power Input Protection
- Current Limit = 3A
- I_ol = (0.7 + 3E-5* @{"Id":"LYKLYEDV\AOLQKRSY","ObjectType":2})
  I_ol = 3A
- 3.3V @ 3A
- 3.3V @ 2000mA
- FTDI
  Signal Muxes
  EEPROM power
  Current Monitors
  Power Sequencing
  LMK04828
- (near U36) Switching Frequency = 1MHz
  Spread Spectrum = On (Random)
  tss = 5ms
  Vout = (R6/R10+1)*Vfb
  Vout = (15.4k/4.87k+1)*0.8V
  Vout = 3.33V

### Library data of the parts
C58 = capcc03260: CAP CER 2.2UF 25V X5R 0402; Manufacturer: TDK Corporation; CompType: Capacitor Ceramic; Tolerance: ±10%; SizeX_mm: 1; SizeY_mm: 0.5; SizeZ_mm: 0.6
C71 C95 C96 = capcc02687: CAP CER 1UF 50V X7R 0805; Manufacturer: TDK Corporation; CompType: Capacitor Ceramic; Tolerance: ±10%; SizeX_mm: 2; SizeY_mm: 1.25; SizeZ_mm: 1.45
C74 = capcc03154: CAP CER 2.2UF 16V X6S 0402; Manufacturer: TDK Corporation; CompType: Capacitor Ceramic; Tolerance: ±10%; SizeX_mm: 1; SizeY_mm: 0.5; SizeZ_mm: 0.65
C97 C98 = capcc03751: CAP CER 1000PF 50V X7R 0603; Manufacturer: TDK Corporation; CompType: Capacitor Ceramic; Tolerance: ±10%; SizeX_mm: 1.6; SizeY_mm: 0.8; SizeZ_mm: 0.9
C126 = capcc03657: CAP CER 10UF 10V X5R 0603; Manufacturer: KYOCERA AVX; CompType: Capacitor Ceramic; Tolerance: ±10%; SizeX_mm: 1.6; SizeY_mm: 0.81; SizeZ_mm: 0.94
C128 = capcc04216: CAP CER 2200PF 50V X7R 0402; Manufacturer: KYOCERA AVX; CompType: Capacitor Ceramic; Tolerance: ±5%; SizeX_mm: 1; SizeY_mm: 0.5; SizeZ_mm: 0.56
C130 C131 C167 C170 = capcc09395: CAP CER 22UF 10V X7S 0805; Manufacturer: TDK Corporation; CompType: Capacitor Ceramic; Tolerance: ±20%; SizeX_mm: 2; SizeY_mm: 1.25; SizeZ_mm: 1.45
C204 = capcc09398: CAP CER 10UF 6.3V X6S 0402; Manufacturer: Murata; CompType: Capacitor Ceramic; Tolerance: ±20%; SizeX_mm: 1; SizeY_mm: 0.5; SizeZ_mm: 0.7
C205 = capcc02244: CAP CER 0.47UF 16V X7S 0402; Manufacturer: TDK Corporation; CompType: Capacitor Ceramic; Tolerance: ±10%; SizeX_mm: 1; SizeY_mm: 0.5; SizeZ_mm: 0.55
D3 = cmp00247: LED GREEN CLEAR CHIP SMD; Manufacturer: Lite-On Inc.; Current Rating (Amps): 20mA; Voltage - Forward (Vf) (Typ): 3.2V; SizeX_mm: 1.6; SizeY_mm: 0.8; SizeZ_mm: 0.65
D4 = cmp00440: 24.4V Clamp 24.6A Ipp Tvs Diode; Manufacturer: Littlefuse; CompType: Diode TVS
D5 = cmp00438: DIODE SCHOTTKY 30V 1A SOD123; Manufacturer: Onsemi; Alt PartNumber: RB160M-30TR; Alt Manufacturer: Rohm Semiconductor
F1 = cmp00082: FUSE BOARD MOUNT 2.5A 32VDC 1206; Manufacturer: Bourns Inc.; Voltage Rating - DC: 32 V; SizeX_mm: 3.1; SizeY_mm: 1.55; SizeZ_mm: 0.6
F2 = cmp00325: EMI Filter Circuits 40 DB 50V 10A; Manufacturer: Murata Electronics
FB1 = dcp00004: 8.5 Ohms @ 100 MHz 1 Power Line Ferrite Bead 0603 (1608 Metric) 8A 4mOhm; Manufacturer: Murata; Impedance: 8.5 Ω; SizeX_mm: 1.6; SizeY_mm: 0.8
FC1 = dcp00001: Feed through capactior 27uF; Manufacturer: Murata; CompType: Feed Thru Cap; Tolerance: ±20%; SizeX_mm: 3.2; SizeY_mm: 1.6; SizeZ_mm: 1.5
J31 = cmp00022: Power Jack, mini, 2.1mm OD, R/A, TH; Manufacturer: Switchcraft
PP1 PP2 = Probe Point: Probe Point that can be used in lue of a test point; UniqueID: cmp00025
Q1 = cmp00159: MOSFET, N-CH, 20 V, 10 A; Manufacturer: Texas Instruments; CompType: FET
R108 = RSMD040200354: RES SMD 100K OHM 5% 1/10W 0402; Manufacturer: Panasonic Electronic Components; CompType: Resistor SMD; Power (Watts): 0.1W, 1/10W; Temperature Coefficient: ±200ppm/°C; SizeX_mm: 1; SizeY_mm: 0.5; SizeZ_mm: 0.4
R109 = RSMD040203665: RES SMD 76.8K OHM 1% 1/10W 0402; Manufacturer: Panasonic Electronic Components; CompType: Resistor SMD; Power (Watts): 0.1W, 1/10W; Temperature Coefficient: ±100ppm/°C; SizeX_mm: 1; SizeY_mm: 0.5; SizeZ_mm: 0.4
R110 = RSMD040200983: RES SMD 17.4K OHM 1% 1/10W 0402; Manufacturer: Panasonic Electronic Components; CompType: Resistor SMD; Power (Watts): 0.1W, 1/10W; Temperature Coefficient: ±100ppm/°C; SizeX_mm: 1; SizeY_mm: 0.5; SizeZ_mm: 0.4
R111 = RSMD040200897: RES SMD 16.2K OHM 1% 1/10W 0402; Manufacturer: Panasonic Electronic Components; CompType: Resistor SMD; Power (Watts): 0.1W, 1/10W; Temperature Coefficient: ±100ppm/°C; SizeX_mm: 1; SizeY_mm: 0.5; SizeZ_mm: 0.4
R112 = RSMD040200311: RES SMD 10K OHM 1% 1/5W 0402; Manufacturer: Panasonic Electronic Components; CompType: Resistor SMD; Power (Watts): 0.2W, 1/5W; Temperature Coefficient: ±100ppm/°C; SizeX_mm: 1; SizeY_mm: 0.5; SizeZ_mm: 0.4
R113 R115 = RSMD040202587: RES SMD 4.7K OHM 1% 1/5W 0402; Manufacturer: Panasonic Electronic Components; CompType: Resistor SMD; Power (Watts): 0.2W, 1/5W; Temperature Coefficient: ±100ppm/°C; SizeX_mm: 1; SizeY_mm: 0.5; SizeZ_mm: 0.4
R114 = RSMD040200802: RES SMD 15.4KOHM 0.1% 1/16W 0402; Manufacturer: Panasonic Electronic Components; SizeX_mm: 1; SizeY_mm: 0.5; SizeZ_mm: 0.4; CompType: Resistor SMD; Power (Watts): 0.063W, 1/16W; Temperature Coefficient: ±15ppm/°C
R116 = RSMD040203748: RES SMD 80.6K OHM 1% 1/10W 0402; Manufacturer: Panasonic Electronic Components; CompType: Resistor SMD; Power (Watts): 0.1W, 1/10W; Temperature Coefficient: ±100ppm/°C; SizeX_mm: 1; SizeY_mm: 0.5; SizeZ_mm: 0.4
R117 = RSMD040202614: RES SMD 4.87KOHM 0.1% 1/16W 0402; Manufacturer: Panasonic Electronic Components; SizeX_mm: 1; SizeY_mm: 0.5; SizeZ_mm: 0.4; CompType: Resistor SMD; Power (Watts): 0.063W, 1/16W; Temperature Coefficient: ±15ppm/°C
R179 = RSMD040200311: RES SMD 10K OHM 1% 1/5W 0402; Manufacturer: Panasonic Electronic Components; SizeX_mm: 1; SizeY_mm: 0.5; SizeZ_mm: 0.4; CompType: Resistor SMD; Power (Watts): 0.2W, 1/5W; Temperature Coefficient: ±100ppm/°C
TP11 = cmp00040: Test Point, Multipurpose, Red, TH; Manufacturer: Keystone
TP12 = cmp00047: Test Point, Multipurpose, Brown, TH; Manufacturer: Keystone
U29 = cmp00157: 12V, 5A, 30mΩ eFuse with Adjustable +/-15% Accurate Current Limit, DRC0010J (VSON-10); Manufacturer: Texas Instruments
U35 = TPS70950DBV: 150-mA, 30-V, ultra-low-IQ, low-dropout voltage regulator with reverse current protection and enable; Manufacturer: Texas Instruments; CompType: LDO
U36 = cmp00201: 3-V to 17-V, 2-A/3-A Low-Noise and Low-Ripple Buck Power Module with Integrated Ferrite Bead Filter Compensation; Manufacturer: Texas Instruments; Switching Frequency: 1/2.2MHz; Max Duty Cycle: 100%; Output Voltage: 0.8-5.5V; Standoff Height: 0mm; CompType: Switcher; Number Of Outputs: 1; Max Supply Voltage: 17V; AEC Category: Q200; TJmax_C: +125°C; Nominal Supply Current: 5mA; Output Type: AdjustableProgrammable; Min Supply Voltage: 3V; AEC Qualified: No

## Sheet ADC34RF7x_Power_Sequencer.SchDoc: Power Sequencer
size 431 x 279 mm; Date: Not shown in title block; ApprovedBy: Not shown in title block; CheckedBy: Not shown in title block; Author: Not shown in title block; CompanyName: Not shown in title block; Engineer: Not shown in title block; Organization: Not shown in title block; Address1: Not shown in title block; Address2: Not shown in title block; Address3: Not shown in title block; Address4: Not shown in title block; DocumentNumber: 1; Revision: Use project parameter SCH_Rev; SheetNumber: 13; SheetTotal: 20; PageSetup: Record=PageOptions¦CenterHorizontal=True¦CenterVertical=True¦PrintScale=1.00¦XCorrection=1.00¦YCorrection=1.00¦PrintKind=0¦BorderSize=5000000¦LeftOffset=0¦BottomOffset=0¦Orientation=2¦PaperLength=1000¦PaperWidth=1000¦Scale=100¦PaperSource=15¦PrintQuality=600¦MediaType=1¦DitherType=10¦PaperKind=Letter¦PrintScaleMode=1
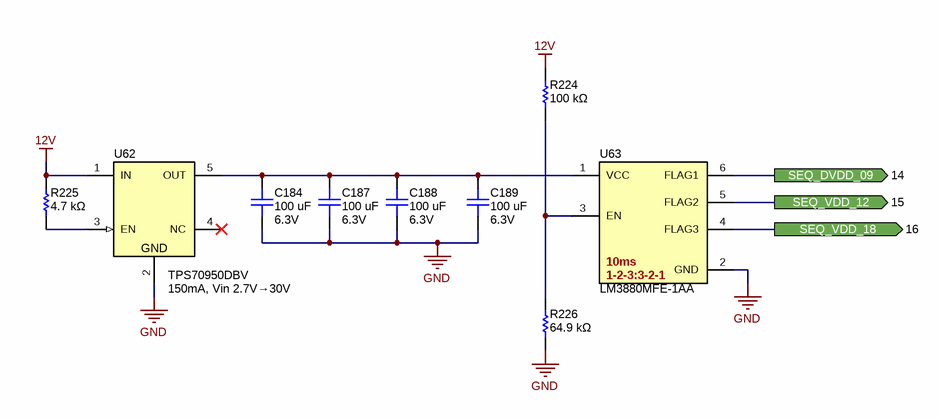
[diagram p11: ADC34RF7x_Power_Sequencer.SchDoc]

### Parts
C184  value 100 uF  Voltage - Rated: 6.3V  [0805L_cap]  (hidden comment: GMC21X5R107M6R3NT)
C187  value 100 uF  Voltage - Rated: 6.3V  [0805L_cap]  (hidden comment: GMC21X5R107M6R3NT)
C188  value 100 uF  Voltage - Rated: 6.3V  [0805L_cap]  (hidden comment: GMC21X5R107M6R3NT)
C189  value 100 uF  Voltage - Rated: 6.3V  [0805L_cap]  (hidden comment: GMC21X5R107M6R3NT)
R224  value 100 kΩ  [0402L]  (hidden comment: ERJ-2GEJ104X)
R225  value 4.7 kΩ  [0402L]  (hidden comment: ERJ-PA2F4701X)
R226  value 64.9 kΩ  [0402L]  (hidden comment: ERA-2AEB6492X)
U62  TPS70950DBV  Text1: 150mA, Vin 2.7V→30V  [DBV0005A]
U63  LM3880MFE-1AA  Text1: 10ms  Sequence: 1-2-3:3-2-1  [DBV0006A]

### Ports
SEQ_DVDD_09 (out, see 14), SEQ_VDD_12 (out, see 15), SEQ_VDD_18 (out, see 16)

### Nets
12V: R224.2 R225.1 U62.1(IN)
GND: C184.1 C187.1 C188.1 C189.1 R226.1 U62.2(GND) U63.2(GND)
SEQ_DVDD_09: U63.6(FLAG1) ; port SEQ_DVDD_09
SEQ_VDD_12: U63.5(FLAG2) ; port SEQ_VDD_12
SEQ_VDD_18: U63.4(FLAG3) ; port SEQ_VDD_18
NetC184_2: C184.2 C187.2 C188.2 C189.2 U62.5(OUT) U63.1(VCC)
NetR224_1: R224.1 R226.2 U63.3(EN)
NetR225_2: R225.2 U62.3(EN)

Not connected (* = marked no-connect by the designer): U62 4(NC)*

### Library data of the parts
C184 C187-C189 = capcc06830: CAP CER 100UF 6.3V X5R 0805; Manufacturer: CAL-CHIP ELECTRONICS, INC.; CompType: Capacitor Ceramic; Tolerance: ±20%; SizeX_mm: 2; SizeY_mm: 1.25
R224 = RSMD040200354: as R108 on sheet ADC34RF7x_Power1_RevA
R225 = RSMD040202587: as R113 on sheet ADC34RF7x_Power1_RevA
R226 = RSMD040203414: RES SMD 64.9KOHM 0.1% 1/16W 0402; Manufacturer: Panasonic Electronic Components; CompType: Resistor SMD; Power (Watts): 0.063W, 1/16W; Temperature Coefficient: ±25ppm/°C; SizeX_mm: 1; SizeY_mm: 0.5; SizeZ_mm: 0.4
U62 = TPS70950DBV: as U35 on sheet ADC34RF7x_Power1_RevA
U63 = LM3880MFE-1AA: 3 Rail Simple Power Sequencer with Fixed Time Delay; Manufacturer: Texas Instruments

## Sheet ADC34RF7x_Power2_RevA.SchDoc: EVM Power 2
size 431 x 279 mm; Date: Not shown in title block; ApprovedBy: Not shown in title block; CheckedBy: Not shown in title block; Author: Not shown in title block; CompanyName: Not shown in title block; DrawnBy: CW; Engineer: Not shown in title block; Organization: Not shown in title block; Address1: Not shown in title block; Address2: Not shown in title block; Address3: Not shown in title block; Address4: Not shown in title block; DocumentNumber: 1; Revision: Use project parameter SCH_Rev; SheetNumber: 14; SheetTotal: 19; PageSetup: Record=PageOptions¦CenterHorizontal=True¦CenterVertical=True¦PrintScale=1.00¦XCorrection=1.00¦YCorrection=1.00¦PrintKind=0¦BorderSize=5000000¦LeftOffset=0¦BottomOffset=0¦Orientation=2¦PaperLength=1000¦PaperWidth=1000¦Scale=100¦PaperSource=15¦PrintQuality=600¦MediaType=1¦DitherType=10¦PaperKind=Letter¦PrintScaleMode=1
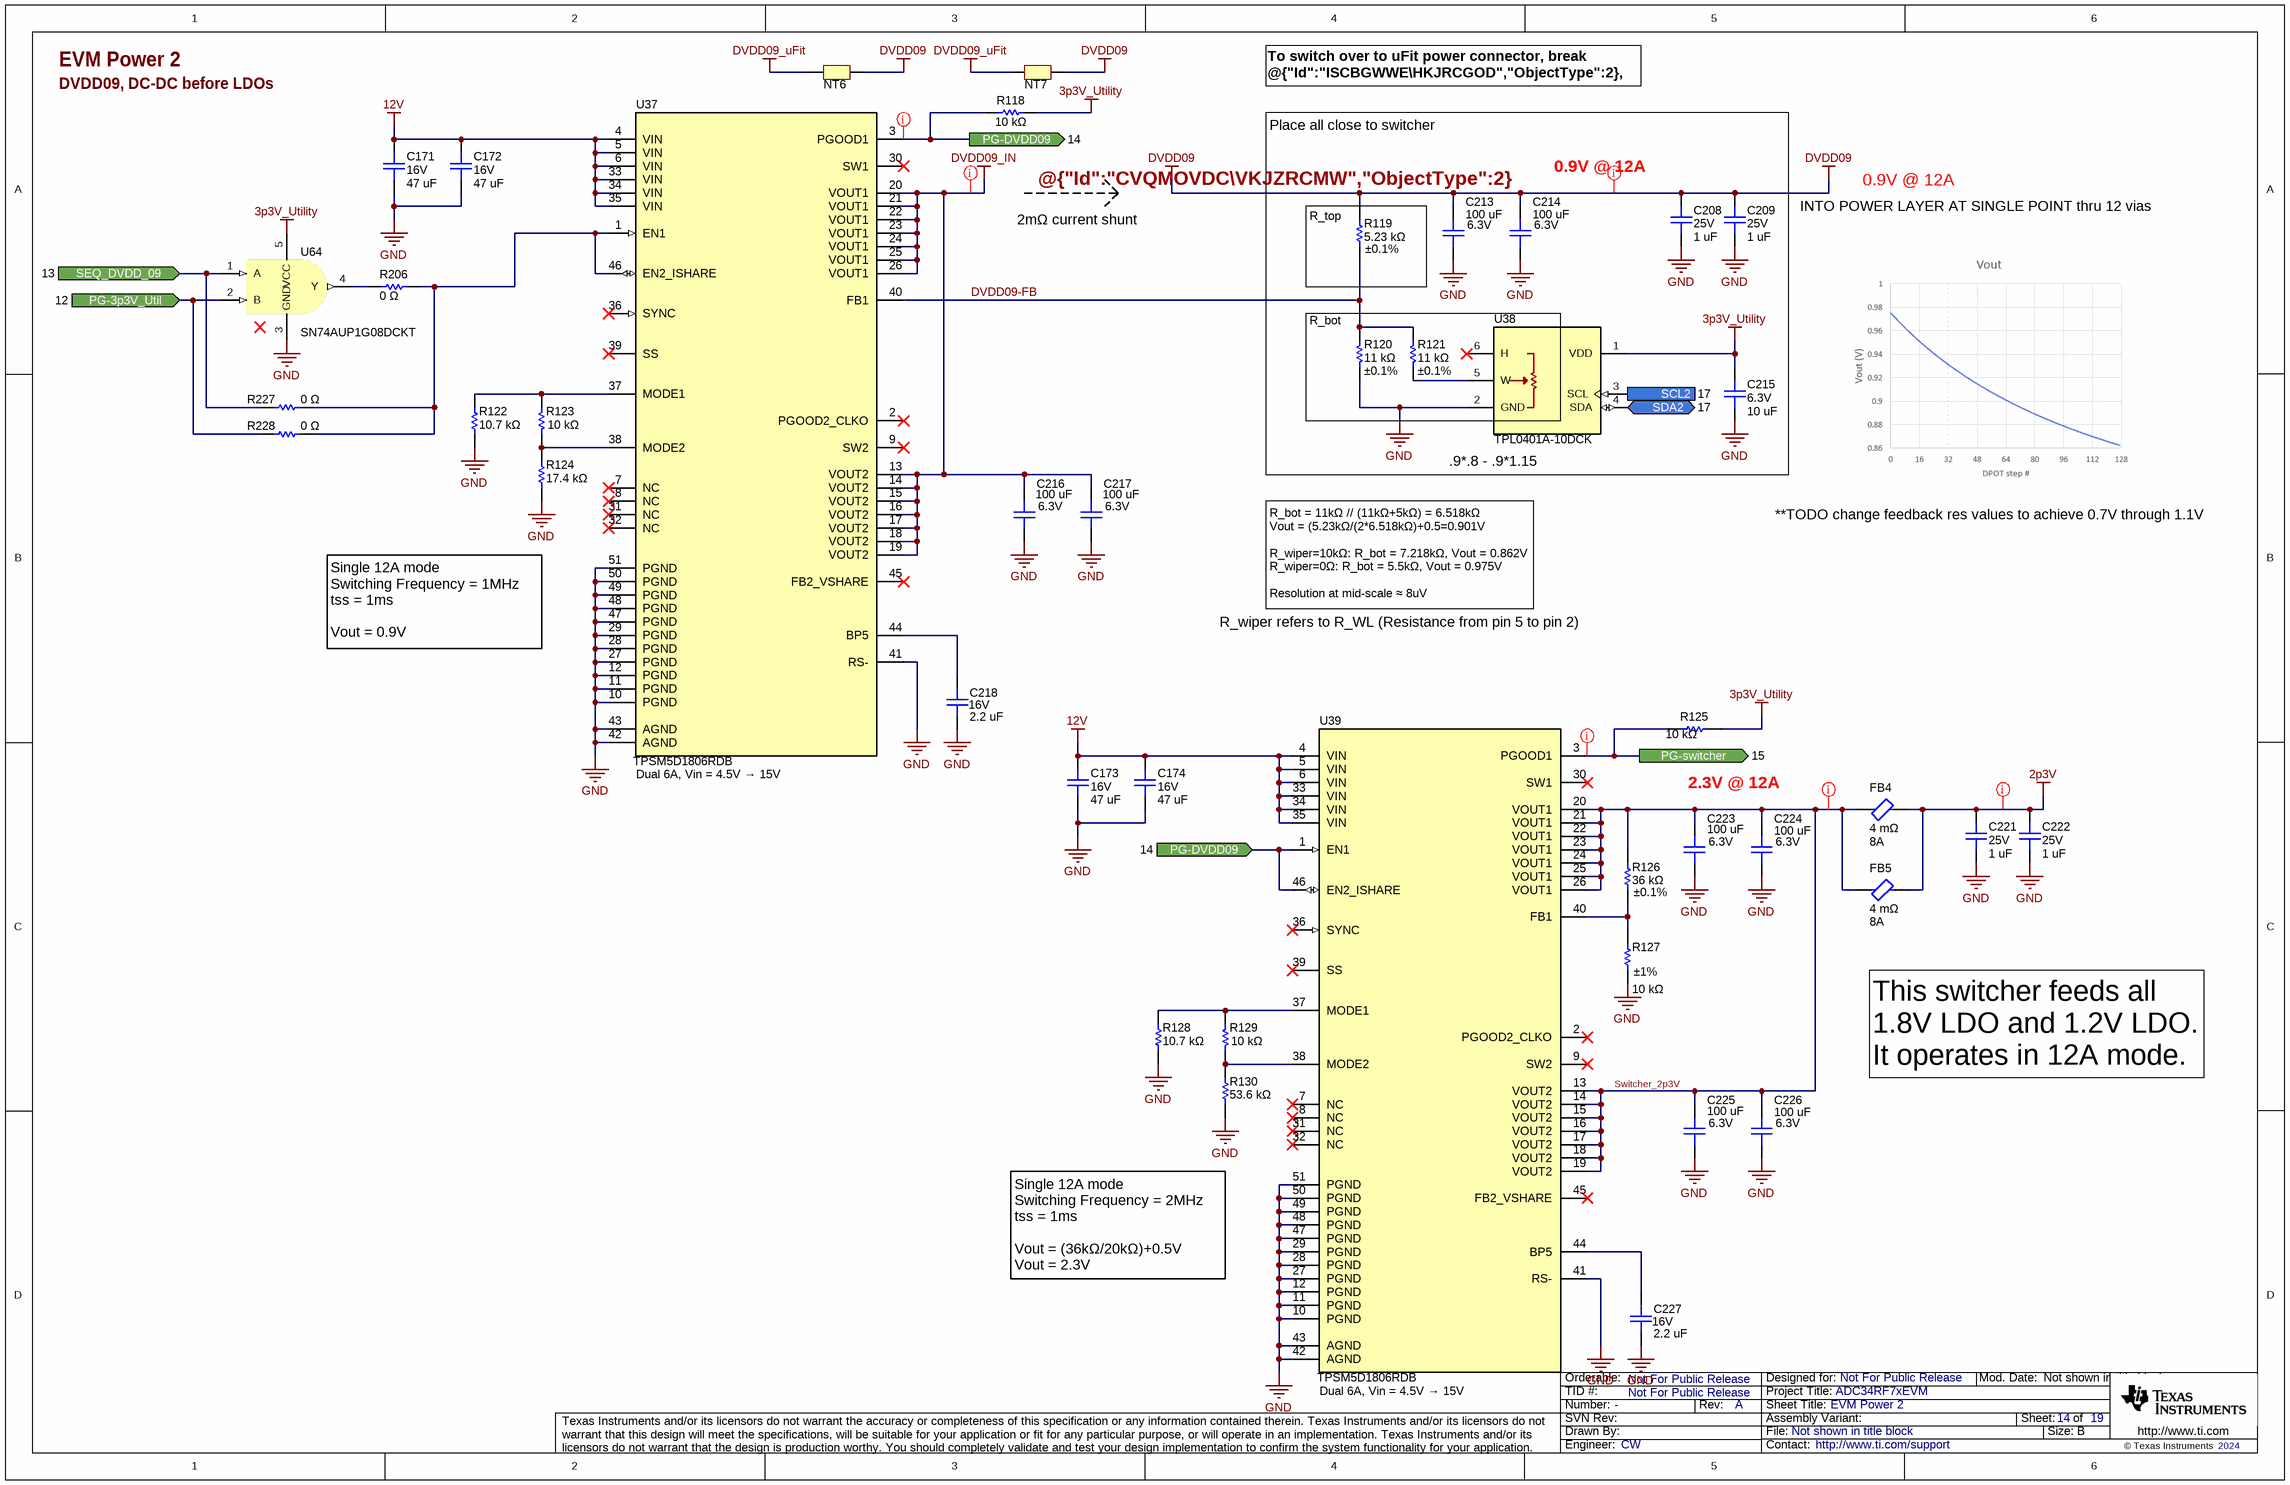
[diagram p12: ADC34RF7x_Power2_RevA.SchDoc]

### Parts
C171  value 47 uF  Voltage - Rated: 16V  [1210L_cap]  (hidden comment: 1210YD476KAT2A)
C172  value 47 uF  Voltage - Rated: 16V  [1210L_cap]  (hidden comment: 1210YD476KAT2A)
C173  value 47 uF  Voltage - Rated: 16V  [1210L_cap]  (hidden comment: 1210YD476KAT2A)
C174  value 47 uF  Voltage - Rated: 16V  [1210L_cap]  (hidden comment: 1210YD476KAT2A)
C208  value 1 uF  Voltage - Rated: 25V  [0402L_cap]  (hidden comment: C1005X5R1E105K050BC)
C209  value 1 uF  Voltage - Rated: 25V  [0402L_cap]  (hidden comment: C1005X5R1E105K050BC)
C213  value 100 uF  Voltage - Rated: 6.3V  [1210L_cap]  (hidden comment: GRT32EC70J107ME13L)
C214  value 100 uF  Voltage - Rated: 6.3V  [1210L_cap]  (hidden comment: GRT32EC70J107ME13L)
C215  value 10 uF  Voltage - Rated: 6.3V  [0402L_cap]  (hidden comment: GRM155C80J106ME11D)
C216  value 100 uF  Voltage - Rated: 6.3V  [1210L_cap]  (hidden comment: GRT32EC70J107ME13L)
C217  value 100 uF  Voltage - Rated: 6.3V  [1210L_cap]  (hidden comment: GRT32EC70J107ME13L)
C218  value 2.2 uF  Voltage - Rated: 16V  [0402L_cap]  (hidden comment: C1005X6S1C225K050BC)
C221  value 1 uF  Voltage - Rated: 25V  [0402L_cap]  (hidden comment: C1005X5R1E105K050BC)
C222  value 1 uF  Voltage - Rated: 25V  [0402L_cap]  (hidden comment: C1005X5R1E105K050BC)
C223  value 100 uF  Voltage - Rated: 6.3V  [1210L_cap]  (hidden comment: GRT32EC70J107ME13L)
C224  value 100 uF  Voltage - Rated: 6.3V  [1210L_cap]  (hidden comment: GRT32EC70J107ME13L)
C225  value 100 uF  Voltage - Rated: 6.3V  [1210L_cap]  (hidden comment: GRT32EC70J107ME13L)
C226  value 100 uF  Voltage - Rated: 6.3V  [1210L_cap]  (hidden comment: GRT32EC70J107ME13L)
C227  value 2.2 uF  Voltage - Rated: 16V  [0402L_cap]  (hidden comment: C1005X6S1C225K050BC)
FB4  Current: 8A  DCR: 4 mΩ  [0603L]  (hidden comment: BLE18PS080SN1D)
FB5  Current: 8A  DCR: 4 mΩ  [0603L]  (hidden comment: BLE18PS080SN1D)
NT6  Net-Tie  [Net-Tie_50milWide_30milLong]  (value not drawn)  (net tie, no BOM)
NT7  Net-Tie  [Net-Tie_50milWide_30milLong]  (value not drawn)  (net tie, no BOM)
R118  value 10 kΩ  [0402L]  (hidden comment: ERJ-PA2F1002X)
R119  value 5.23 kΩ  Tolerance: ±0.1%  [0402L]  (hidden comment: ERA-2AEB5231X)
R120  value 11 kΩ  Tolerance: ±0.1%  [0402L]  (hidden comment: ERA-2AEB113X)
R121  value 11 kΩ  Tolerance: ±0.1%  [0402L]  (hidden comment: ERA-2AEB113X)
R122  value 10.7 kΩ  [0402L]  (hidden comment: ERA-2APB1072X)
R123  value 10 kΩ  [0402L]  (hidden comment: ERJ-PA2F1002X)
R124  value 17.4 kΩ  [0402L]  (hidden comment: ERJ-2RKF1742X)
R125  value 10 kΩ  [0402L]  (hidden comment: ERJ-PA2F1002X)
R126  value 36 kΩ  Tolerance: ±0.1%  [0402L]  (hidden comment: ERA-2APB363X)
R127  value 10 kΩ  Tolerance: ±1%  [0402L]  (hidden comment: ERJ-PA2F1002X)
R128  value 10.7 kΩ  [0402L]  (hidden comment: ERA-2APB1072X)
R129  value 10 kΩ  [0402L]  (hidden comment: ERJ-PA2F1002X)
R130  value 53.6 kΩ  [0402L]  (hidden comment: ERJ-2RKF5362X)
R206  value 0 Ω  [0402L]  (hidden comment: ERJ-2GE0R00X)
R227  value 0 Ω  [0402L]  (hidden comment: ERJ-2GE0R00X)
R228  value 0 Ω  [0402L]  (hidden comment: ERJ-2GE0R00X)
U37  Text1: Dual 6A, Vin = 4.5V → 15V  [RDB0051A]  (hidden comment: TPSM5D1806RDB)
U38  TPL0401A-10DCK  [DCK0006A]
U39  Text1: Dual 6A, Vin = 4.5V → 15V  [RDB0051A]  (hidden comment: TPSM5D1806RDB)
U64  SN74AUP1G08DCKT  [DCK0005A]

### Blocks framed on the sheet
R_top: R119
R_bot: R120 R121 U38

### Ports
PG-3p3V_Util (in, see 12), PG-DVDD09 (in, see 14), PG-DVDD09 (out, see 14), PG-switcher (out, see 15), SCL2 (in, see 17), SDA2 (bidir, see 17), SEQ_DVDD_09 (in, see 13)

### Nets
2p3V: C221.2 C222.2 FB4.2 FB5.2
3p3V_Utility: C215.2 R118.1 R125.1 U38.1(VDD) U64.5(VCC)
12V: C171.2 C172.2 C173.2 C174.2 U37.4(VIN) U37.5(VIN) U37.6(VIN) U37.33(VIN) U37.34(VIN) U37.35(VIN) U39.4(VIN) U39.5(VIN) U39.6(VIN) U39.33(VIN) U39.34(VIN) U39.35(VIN)
DVDD09: C208.2 C209.2 C213.2 C214.2 NT6.1 NT7.1 R119.2
DVDD09_IN: C216.2 C217.2 U37.13(VOUT2) U37.14(VOUT2) U37.15(VOUT2) U37.16(VOUT2) U37.17(VOUT2) U37.18(VOUT2) U37.19(VOUT2) U37.20(VOUT1) U37.21(VOUT1) U37.22(VOUT1) U37.23(VOUT1) U37.24(VOUT1) U37.25(VOUT1) U37.26(VOUT1)
DVDD09_uFit: NT6.2 NT7.2
GND: C171.1 C172.1 C173.1 C174.1 C208.1 C209.1 C213.1 C214.1 C215.1 C216.1 C217.1 C218.1 C221.1 C222.1 C223.1 C224.1 C225.1 C226.1 C227.1 R120.1 R122.1 R124.1 R127.1 R128.1 R130.1 U37.10(PGND) U37.11(PGND) U37.12(PGND) U37.27(PGND) U37.28(PGND) U37.29(PGND) U37.41(RS-) U37.42(AGND) U37.43(AGND) U37.47(PGND) U37.48(PGND) U37.49(PGND) U37.50(PGND) U37.51(PGND) U38.2(GND) U39.10(PGND) U39.11(PGND) U39.12(PGND) U39.27(PGND) U39.28(PGND) U39.29(PGND) U39.41(RS-) U39.42(AGND) U39.43(AGND) U39.47(PGND) U39.48(PGND) U39.49(PGND) U39.50(PGND) U39.51(PGND) U64.3(GND)
DVDD09-FB: R119.1 R120.2 R121.2 U37.40(FB1)
PG-3p3V_Util: R228.1 U64.2(B) ; port PG-3p3V_Util
PG-DVDD09: R118.2 U37.3(PGOOD1) U39.1(EN1) U39.46(EN2_ISHARE) ; port PG-DVDD09
PG-switcher: R125.2 U39.3(PGOOD1) ; port PG-switcher
SCL2: U38.3(SCL) ; port SCL2
SDA2: U38.4(SDA) ; port SDA2
SEQ_DVDD_09: R227.1 U64.1(A) ; port SEQ_DVDD_09
Switcher_2p3V: C223.2 C224.2 C225.2 C226.2 FB4.1 FB5.1 R126.2 U39.13(VOUT2) U39.14(VOUT2) U39.15(VOUT2) U39.16(VOUT2) U39.17(VOUT2) U39.18(VOUT2) U39.19(VOUT2) U39.20(VOUT1) U39.21(VOUT1) U39.22(VOUT1) U39.23(VOUT1) U39.24(VOUT1) U39.25(VOUT1) U39.26(VOUT1)
NetC218_2: C218.2 U37.44(BP5)
NetC227_2: C227.2 U39.44(BP5)
NetR121_1: R121.1 U38.5(W)
NetR122_2: R122.2 R123.2 U37.37(MODE1)
NetR123_1: R123.1 R124.2 U37.38(MODE2)
NetR126_1: R126.1 R127.2 U39.40(FB1)
NetR128_2: R128.2 R129.2 U39.37(MODE1)
NetR129_1: R129.1 R130.2 U39.38(MODE2)
NetR206_1: R206.1 U64.4(Y)
NetR206_2: R206.2 R227.2 R228.2 U37.1(EN1) U37.46(EN2_ISHARE)

Not connected (* = marked no-connect by the designer): U37 2(PGOOD2_CLKO)* 7(NC)* 8(NC)* 9(SW2)* 30(SW1)* 31(NC)* 32(NC)* 36(SYNC)* 39(SS)* 45(FB2_VSHARE)*; U38 6(H)*; U39 2(PGOOD2_CLKO)* 7(NC)* 8(NC)* 9(SW2)* 30(SW1)* 31(NC)* 32(NC)* 36(SYNC)* 39(SS)* 45(FB2_VSHARE)*

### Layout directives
net class Power_DVDD09: DVDD09, DVDD09_IN
net class Power_Switcher_2p3V: 2p3V, Switcher_2p3V
net class Power sequencing: PG-DVDD09, PG-switcher

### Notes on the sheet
- DVDD09, DC-DC before LDOs
- To switch over to uFit power connector, break @{"Id":"ISCBGWWE\HKJRCGOD","ObjectType":2}, @{"Id":"ISCBGWWE\JZOVXZYS","ObjectType":2} and @{"Id":"CVQMOVDC\VKJZRCMW","ObjectType":2} (2mΩ current shunt) for DVDD
- 0.9V @ 12A
- @{"Id":"CVQMOVDC\VKJZRCMW","ObjectType":2}
- 2mΩ current shunt
- INTO POWER LAYER AT SINGLE POINT thru 12 vias
- Place all close to switcher
- (near U38) .9*.8 - .9*1.15
- **TODO change feedback res values to achieve 0.7V through 1.1V
- R_bot = 11kΩ // (11kΩ+5kΩ) = 6.518kΩ
  Vout = (5.23kΩ/(2*6.518kΩ)+0.5=0.901V
  R_wiper=10kΩ: R_bot = 7.218kΩ, Vout = 0.862V
  R_wiper=0Ω: R_bot = 5.5kΩ, Vout = 0.975V
  Resolution at mid-scale ≈ 8uV
- R_wiper refers to R_WL (Resistance from pin 5 to pin 2)
- Single 12A mode
  Switching Frequency = 1MHz
  tss = 1ms
  Vout = 0.9V
- 2.3V @ 12A
- This switcher feeds all 1.8V LDO and 1.2V LDO. It operates in 12A mode.
- Single 12A mode
  Switching Frequency = 2MHz
  tss = 1ms
  Vout = (36kΩ/20kΩ)+0.5V
  Vout = 2.3V

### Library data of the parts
C171-C174 = capcc03627: CAP CER 47UF 16V X5R 1210; Manufacturer: KYOCERA AVX; CompType: Capacitor Ceramic; Tolerance: ±10%; SizeX_mm: 3.35; SizeY_mm: 2.5; SizeZ_mm: 2.8
C208 C209 C221 C222 = capcc02750: CAP CER 1UF 25V X5R 0402; Manufacturer: TDK Corporation; CompType: Capacitor Ceramic; Tolerance: ±10%; SizeX_mm: 1; SizeY_mm: 0.5; SizeZ_mm: 0.55
C213 C214 C216 C217 C223-C226 = capcc09408: CAP CER 100UF 6.3V X7S 1210; Manufacturer: Murata; SizeY_mm: 2.5; CompType: Capacitor Ceramic; SizeZ_mm: 2.8; SizeX_mm: 3.2; Tolerance: ±20%
C215 = capcc09398: as C204 on sheet ADC34RF7x_Power1_RevA
C218 C227 = capcc03154: as C74 on sheet ADC34RF7x_Power1_RevA
FB4 FB5 = dcp00004: as FB1 on sheet ADC34RF7x_Power1_RevA
NT6 NT7 = CMP-0078142-6: Single point connection between nets.
R118 R125 = RSMD040200311: as R179 on sheet ADC34RF7x_Power1_RevA
R119 = RSMD040202950: RES SMD 5.23KOHM 0.1% 1/16W 0402; Manufacturer: Panasonic Electronic Components; CompType: Resistor SMD; Power (Watts): 0.063W, 1/16W; Temperature Coefficient: ±25ppm/°C; SizeX_mm: 1; SizeY_mm: 0.5; SizeZ_mm: 0.4
R120 R121 = RSMD040200413: RES SMD 11K OHM 0.1% 1/16W 0402; Manufacturer: Panasonic Electronic Components; CompType: Resistor SMD; Power (Watts): 0.063W, 1/16W; Temperature Coefficient: ±25ppm/°C; SizeX_mm: 1; SizeY_mm: 0.5; SizeZ_mm: 0.4
R122 R128 = RSMD040200348: RES SMD 10.7KOHM 0.1% 1/16W 0402; Manufacturer: Panasonic Electronic Components; CompType: Resistor SMD; Power (Watts): 0.063W, 1/16W; Temperature Coefficient: ±15ppm/°C; SizeX_mm: 1; SizeY_mm: 0.5; SizeZ_mm: 0.4
R123 R127 R129 = RSMD040200311: as R112 on sheet ADC34RF7x_Power1_RevA
R124 = RSMD040200983: as R110 on sheet ADC34RF7x_Power1_RevA
R126 = RSMD040202348: RES SMD 36K OHM 0.1% 1/16W 0402; Manufacturer: Panasonic Electronic Components; CompType: Resistor SMD; Power (Watts): 0.063W, 1/16W; Temperature Coefficient: ±15ppm/°C; SizeX_mm: 1; SizeY_mm: 0.5; SizeZ_mm: 0.4
R130 = RSMD040203089: RES SMD 53.6K OHM 1% 1/10W 0402; Manufacturer: Panasonic Electronic Components; CompType: Resistor SMD; Power (Watts): 0.1W, 1/10W; Temperature Coefficient: ±100ppm/°C; SizeX_mm: 1; SizeY_mm: 0.5; SizeZ_mm: 0.4
R206 R227 R228 = RSMD040200001: as R60 on sheet ADC34RF7x_MUX_RevA
U37 U39 = cmp00235: 4.5-V to 15-V Input, Dual 6-A / Single 12-A Output Power Module; Manufacturer: Texas Instruments; CompType: Switcher
U38 = TPL0401A-10DCK: 128-tap single-channel digital potentiometer (digipot) with I2C interface (address 0101110); Alternate PartNumber: TPL0401A-10DCKT; Manufacturer: Texas Instruments; SymbolCreator: Altium; SizeArea_mm2: 4.2; SizeAreaWB_mm2: 9.3; U/M: EA; UniqueID: cmp00230
U64 = cmp00268: SN74AUP1G08 Low-Power Single 2-Input Positive-AND Gate; Manufacturer: Texas Instruments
